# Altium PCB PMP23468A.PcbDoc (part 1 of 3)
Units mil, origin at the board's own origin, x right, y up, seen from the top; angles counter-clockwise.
Board outline 5250 x 3500 mil, 6 copper layers (Top Layer, Signal Layer 1, Signal Layer 2, Signal Layer 3, Signal Layer 4, Bottom Layer), stack 61.8 mil thick; 157 components, 73 nets, 403 pads, 842 vias.
Unrouted connection lines stored in the file: 3.
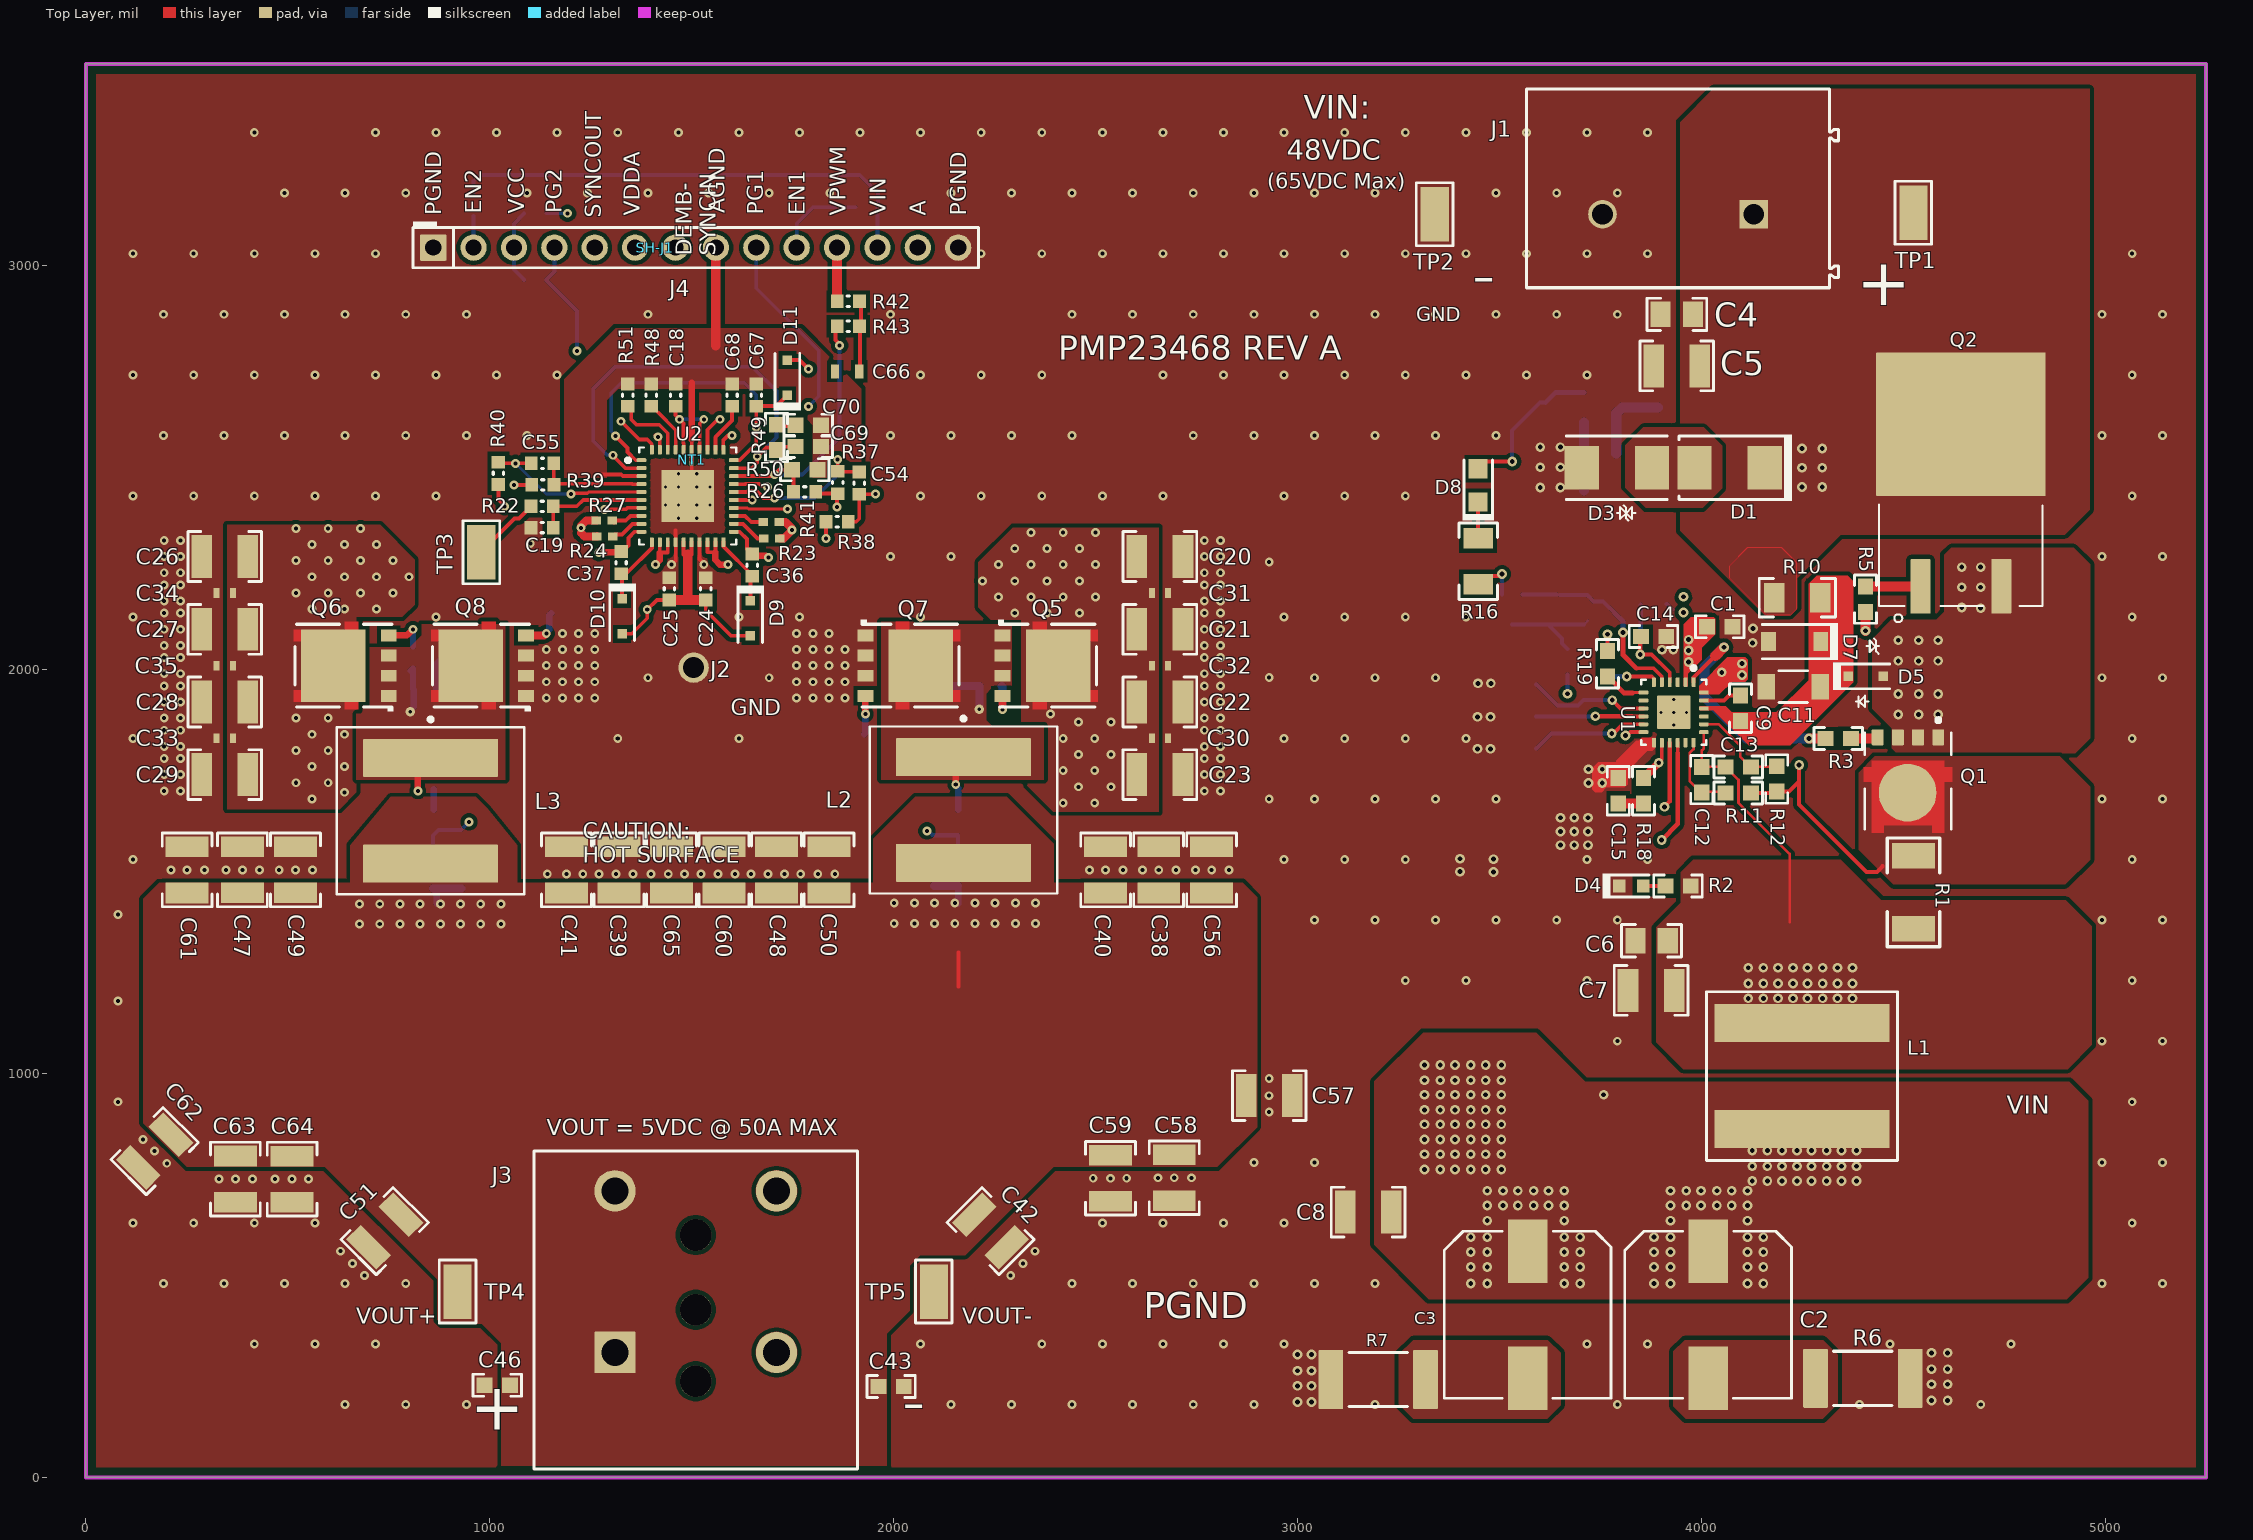
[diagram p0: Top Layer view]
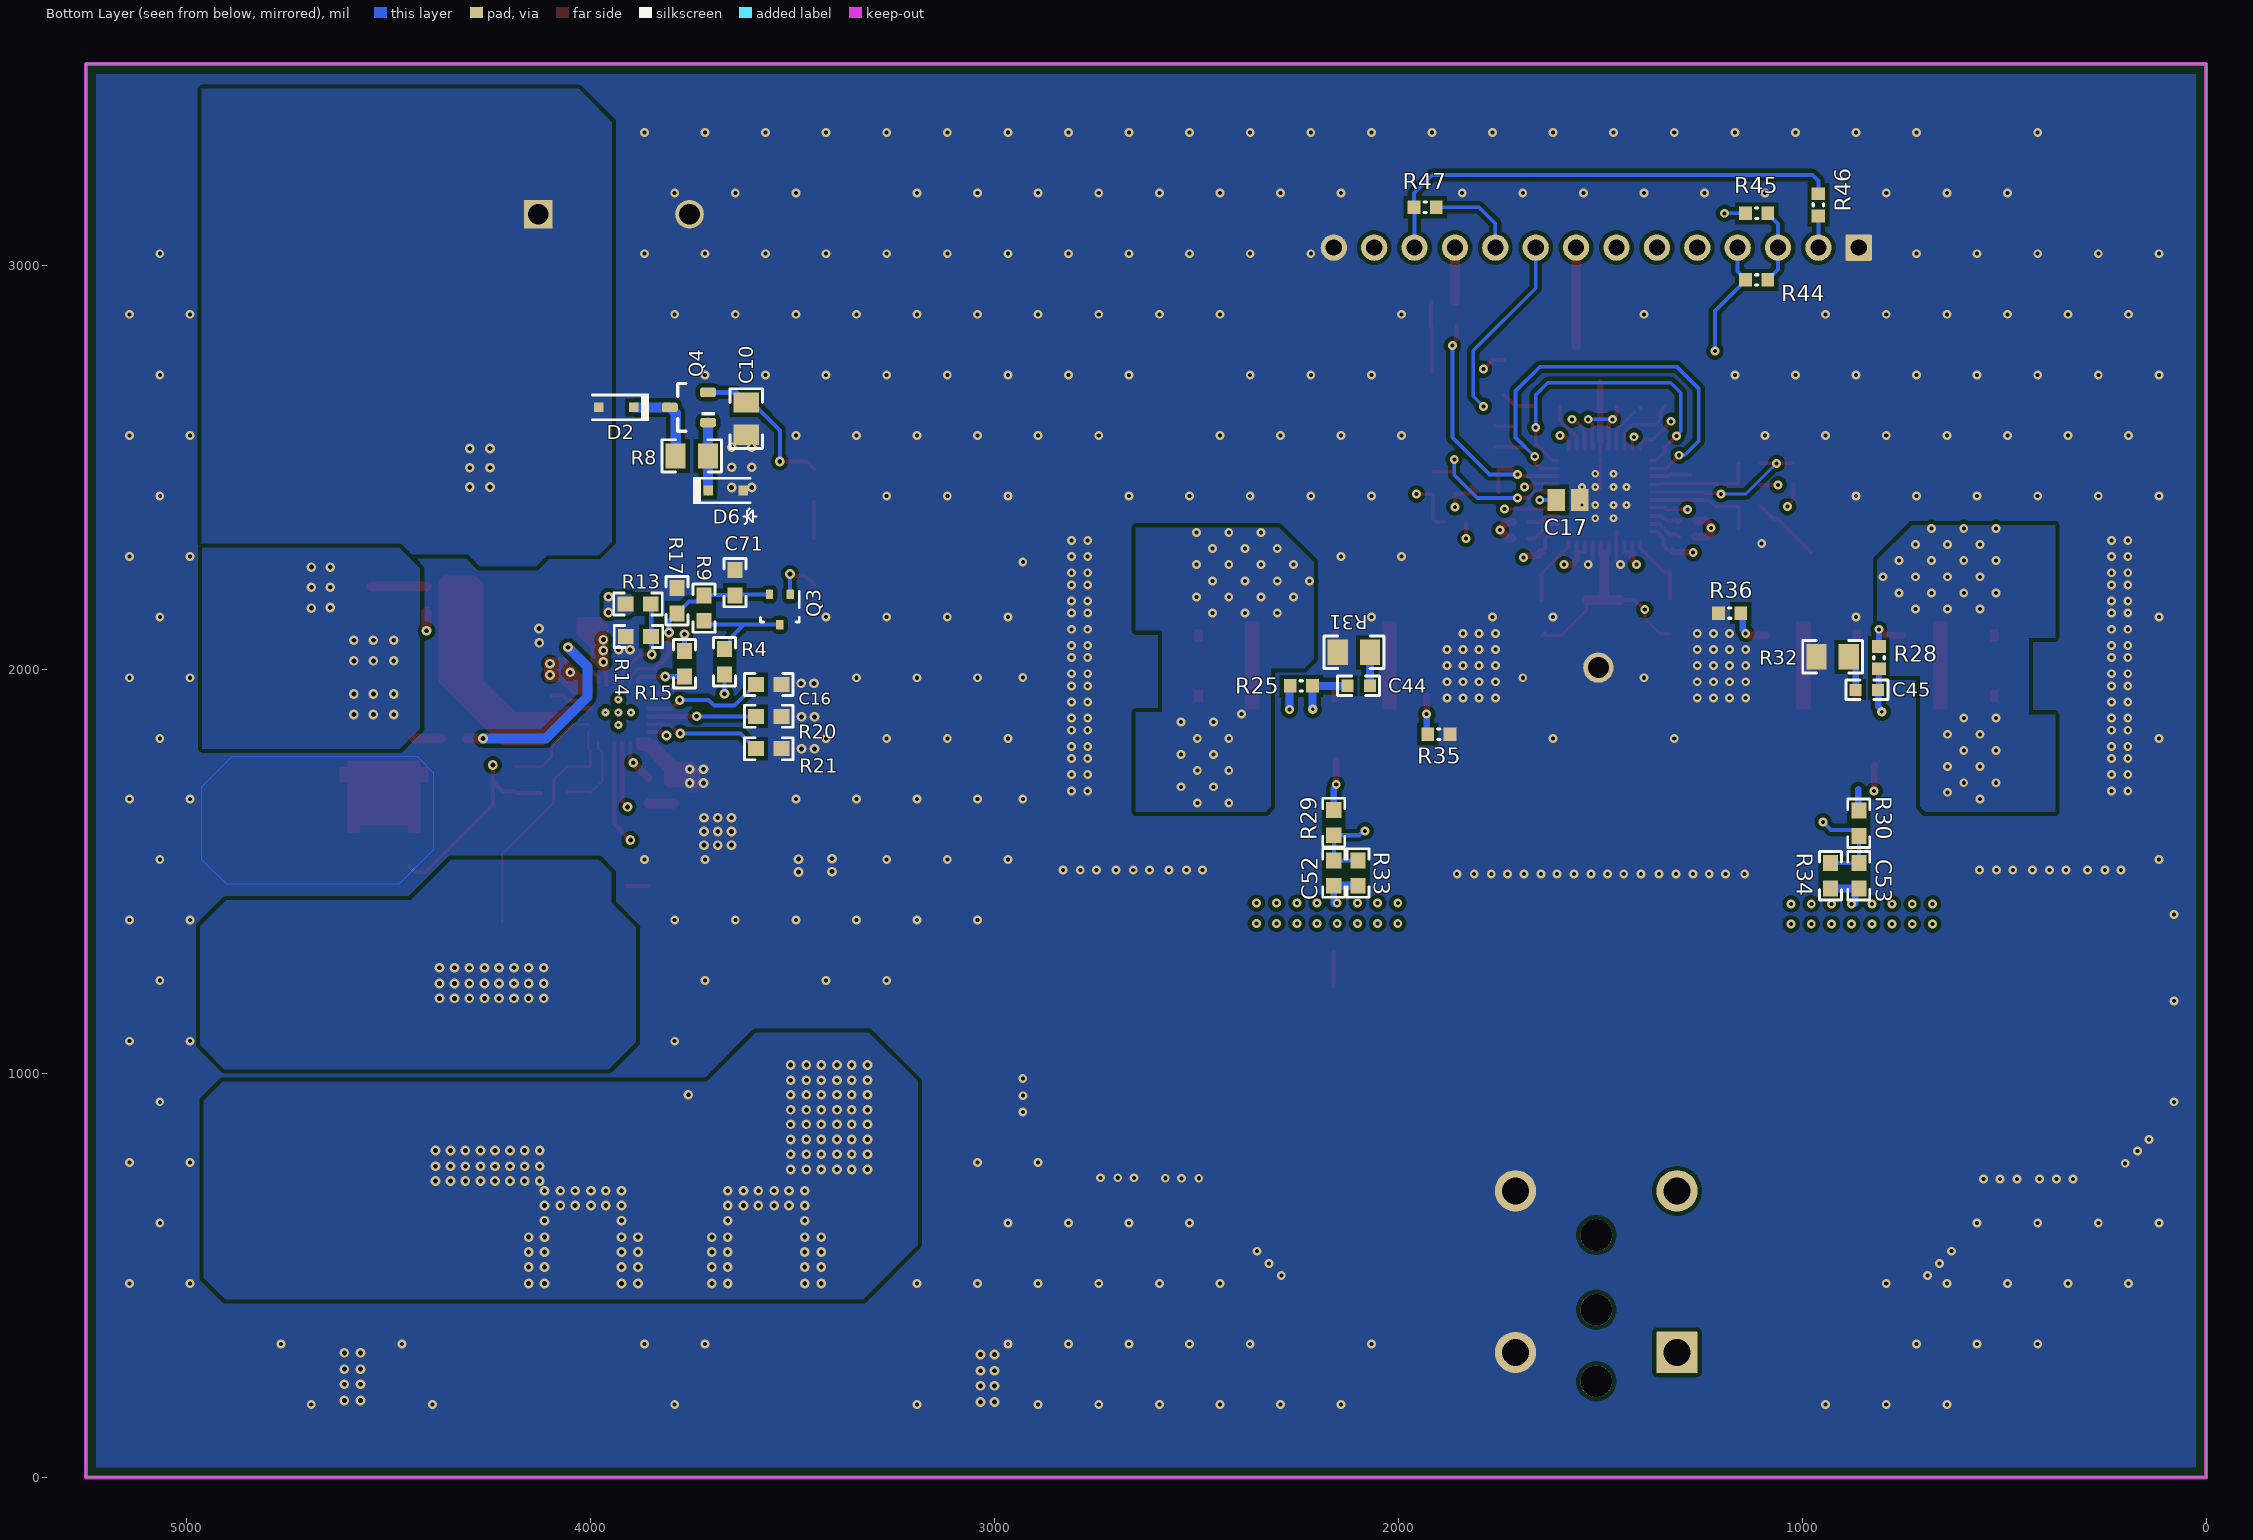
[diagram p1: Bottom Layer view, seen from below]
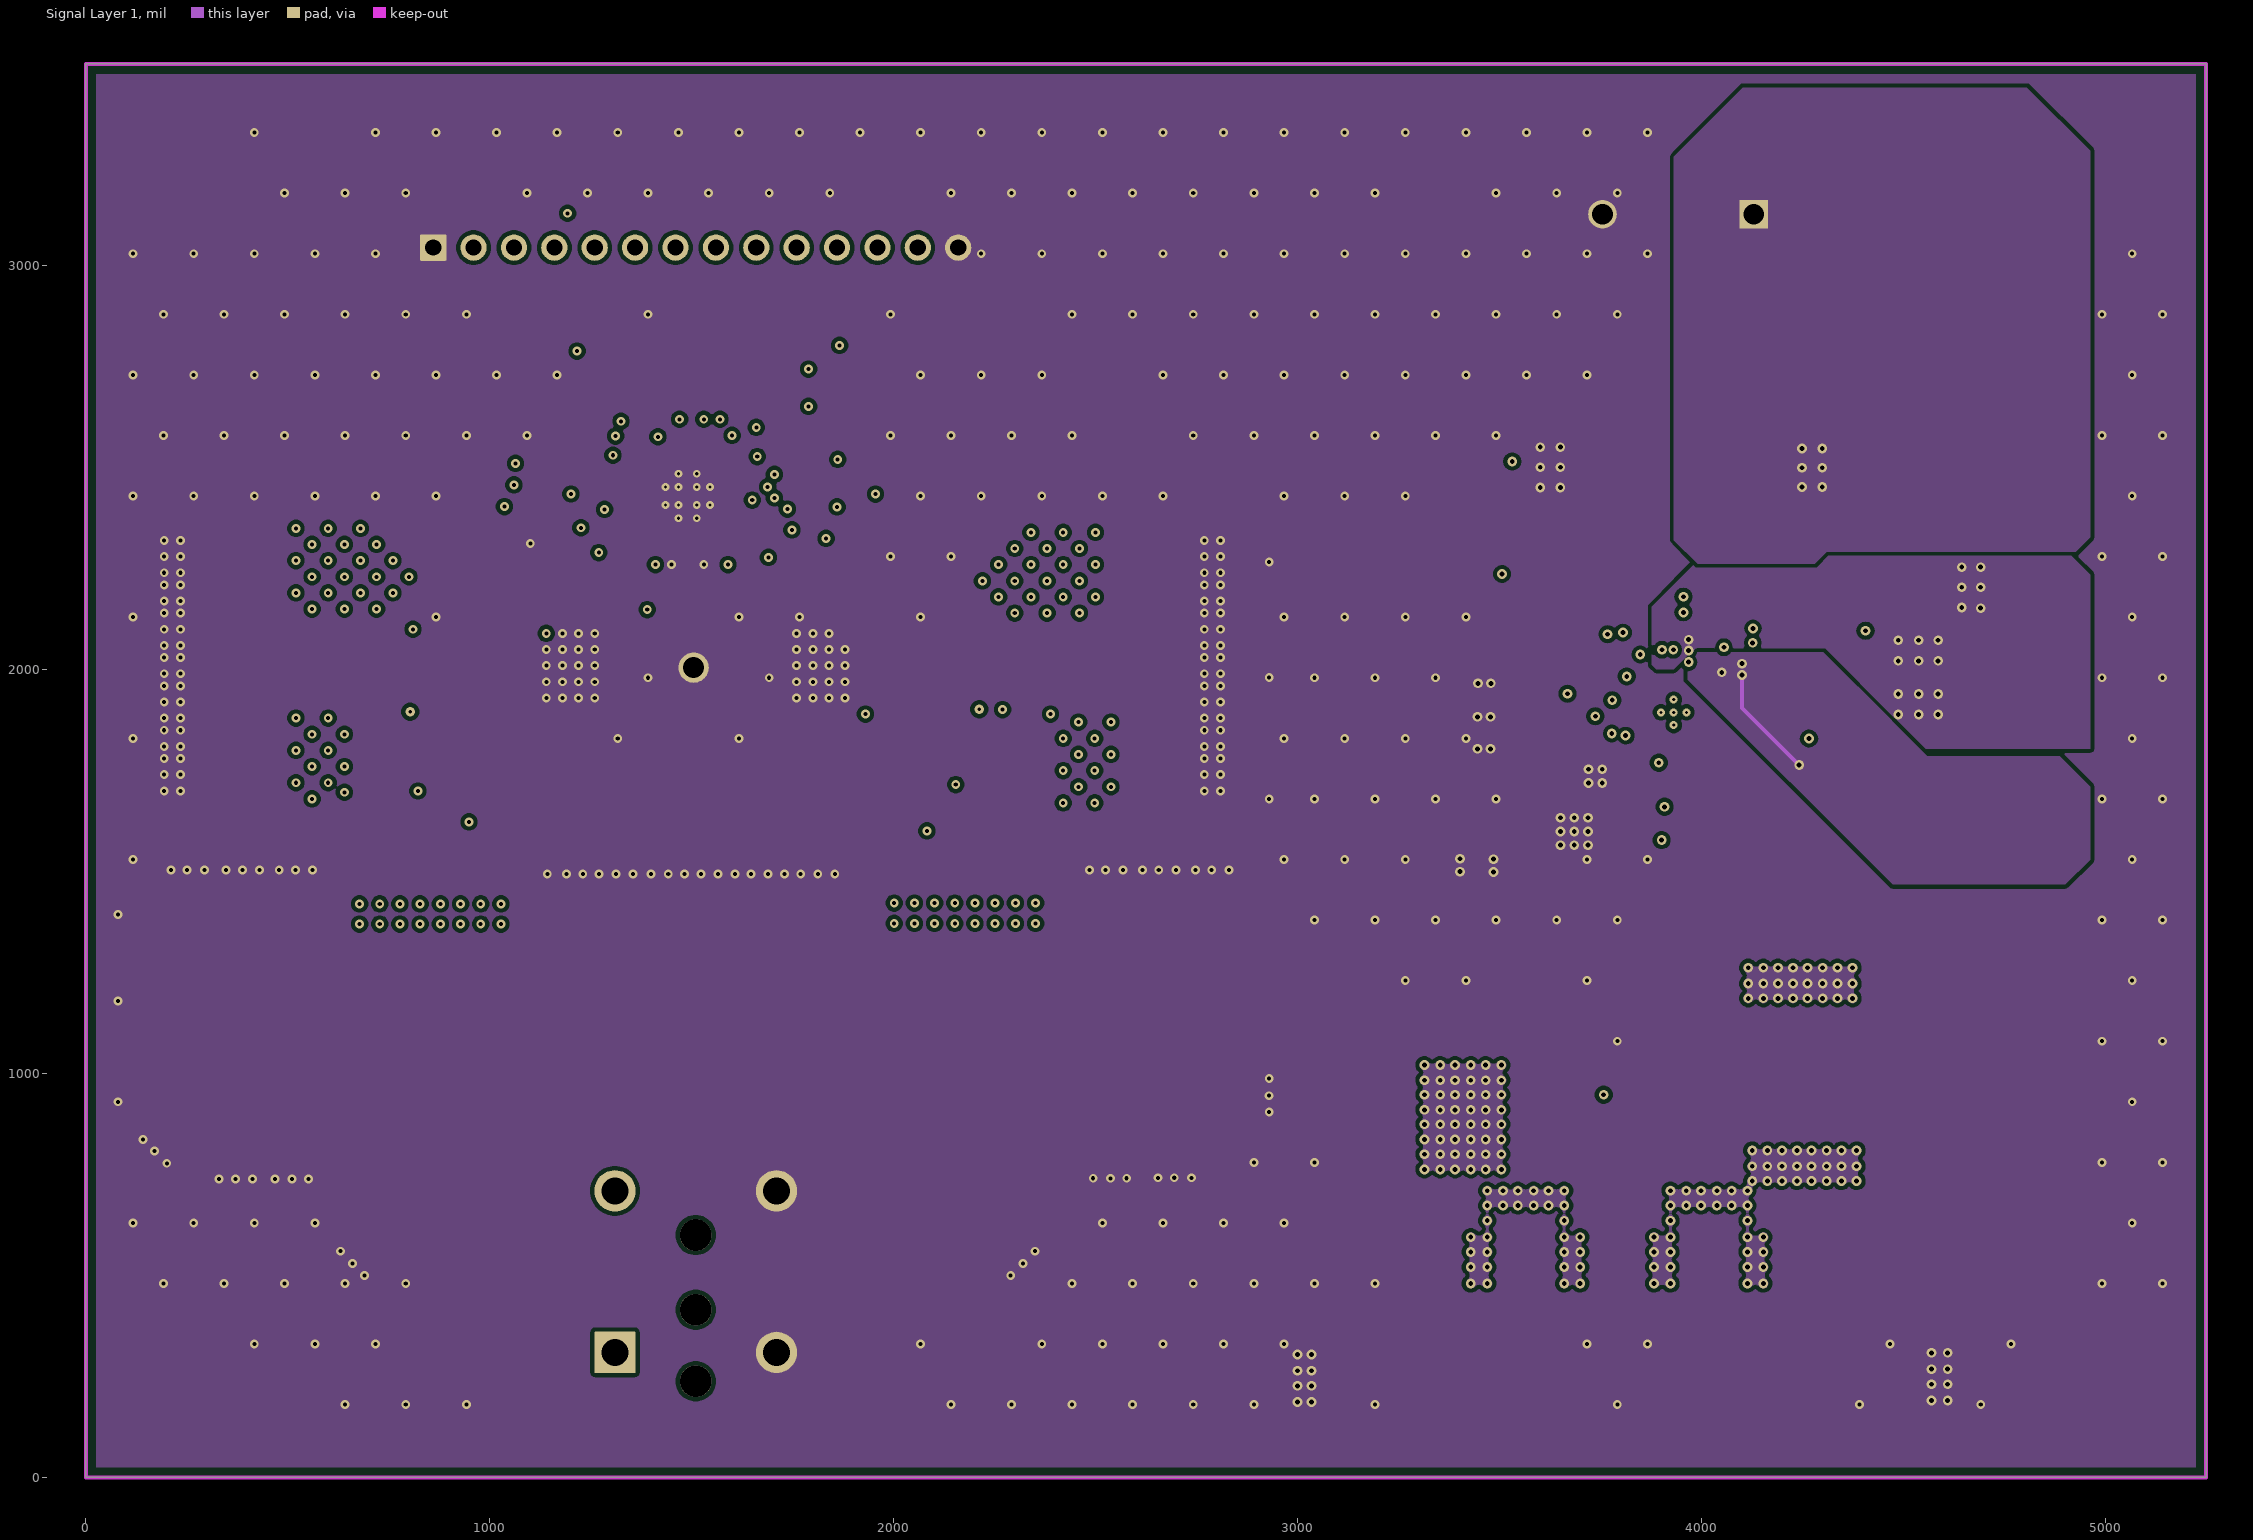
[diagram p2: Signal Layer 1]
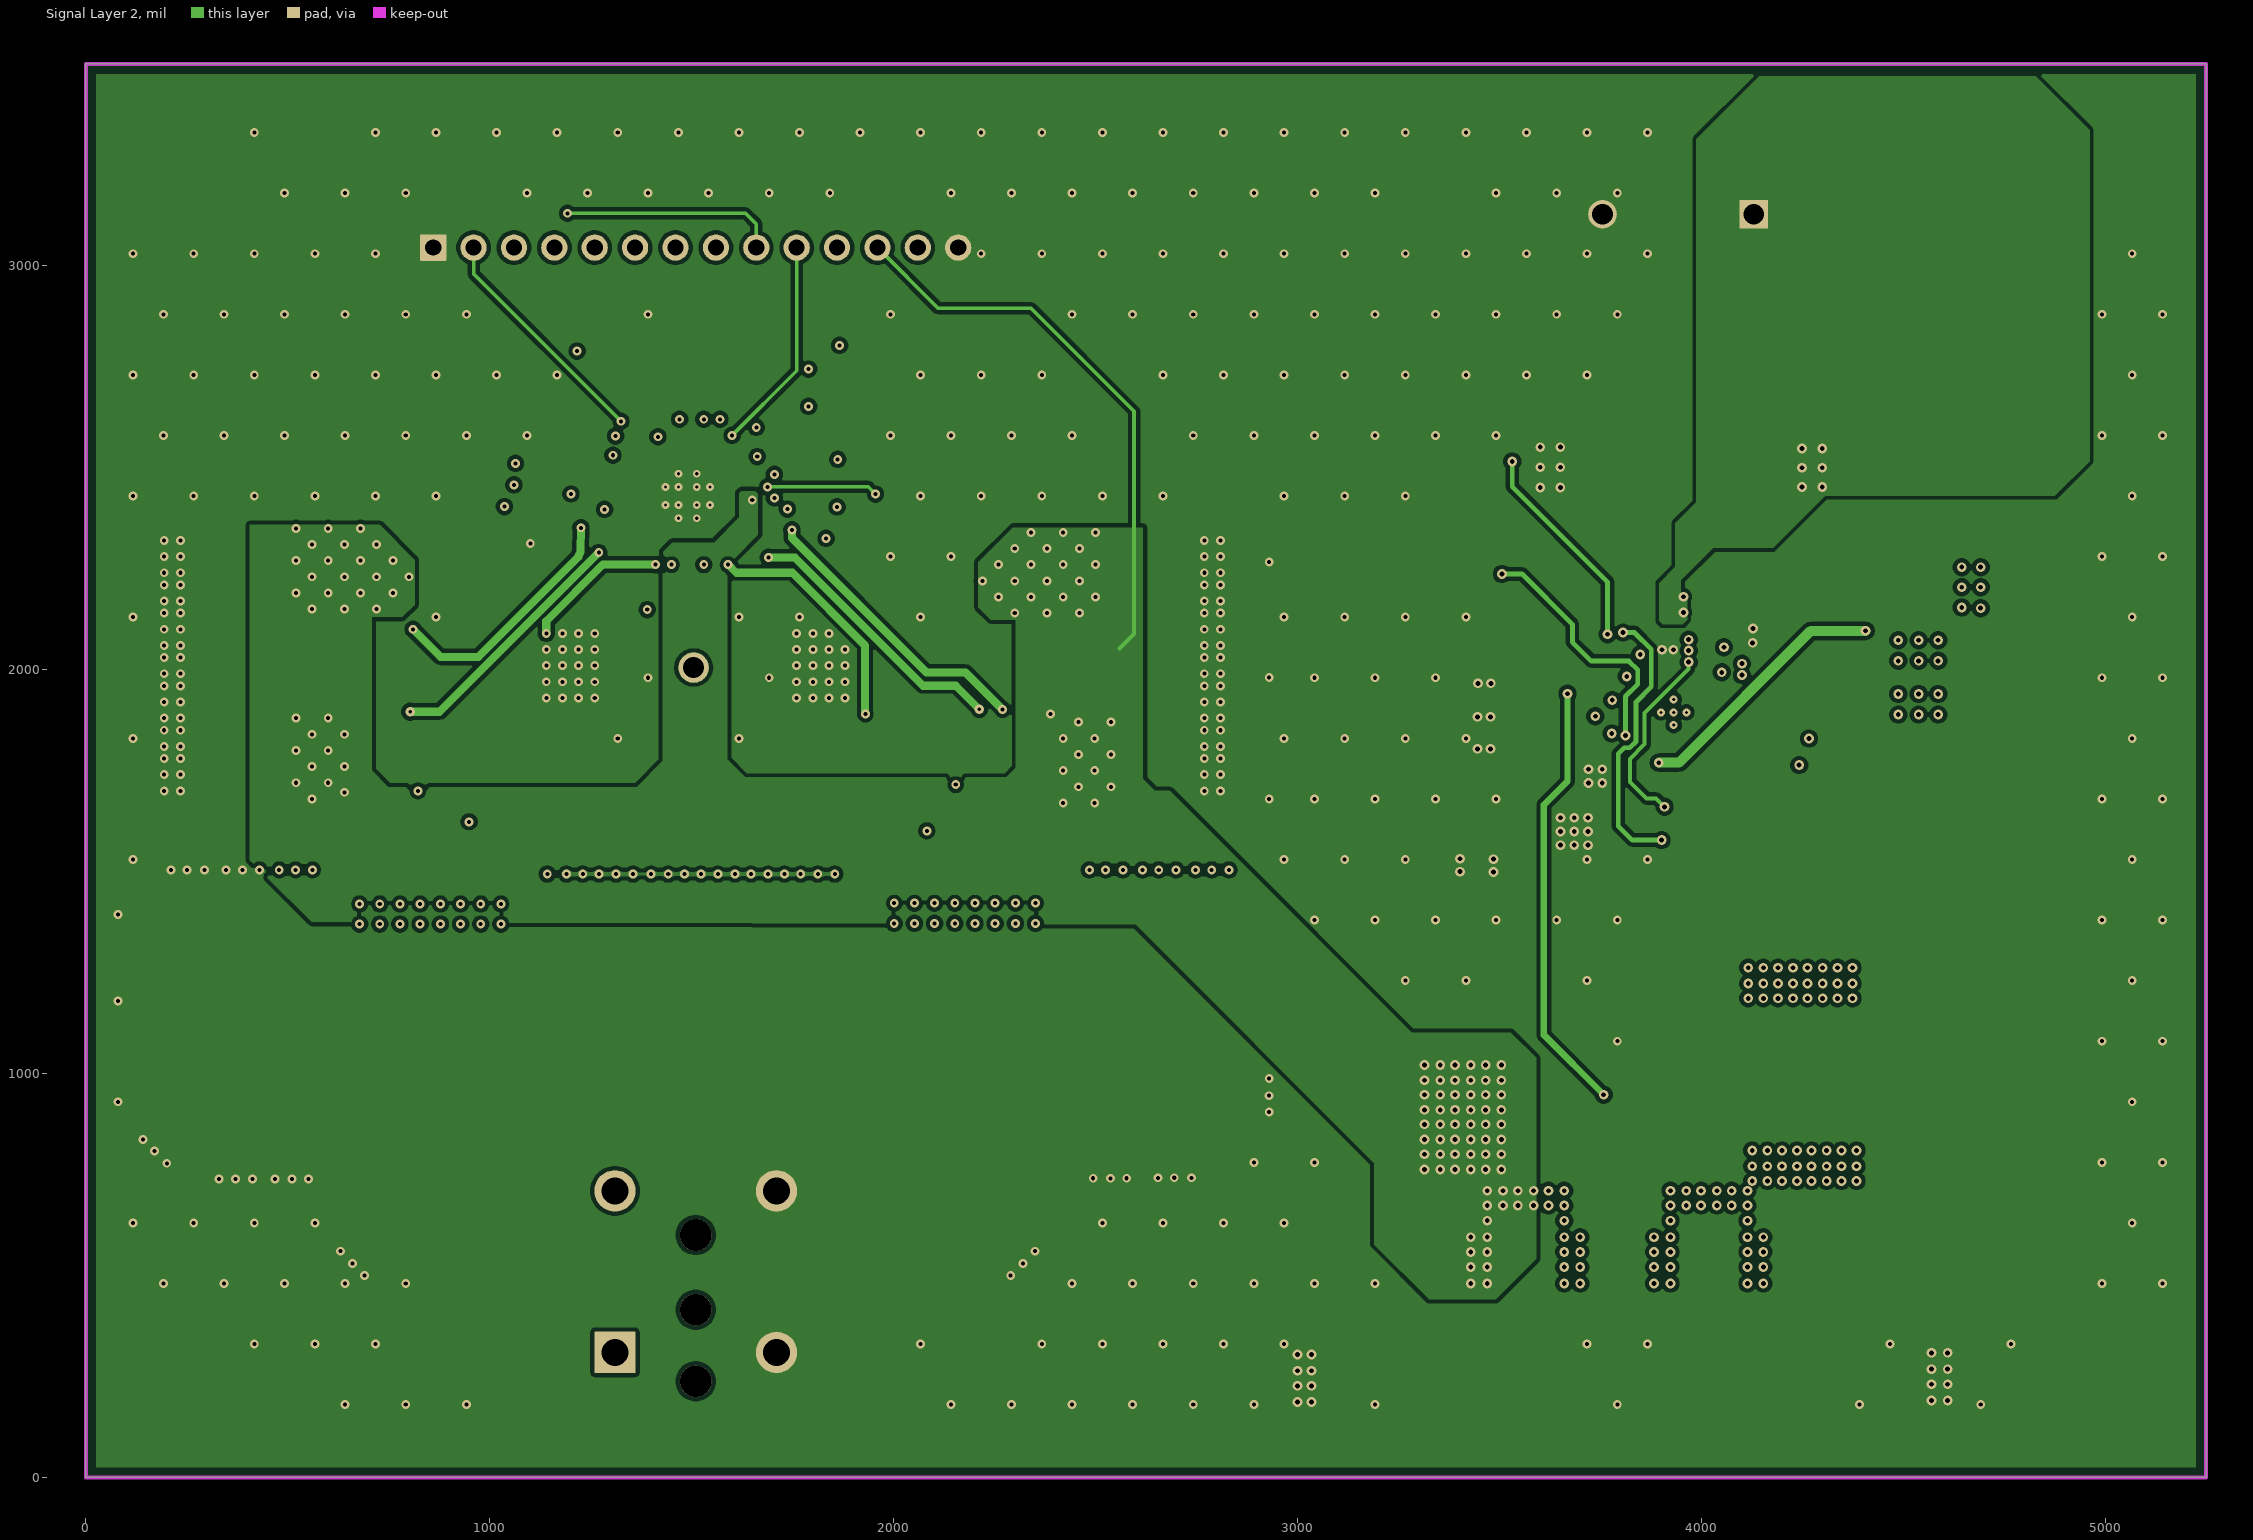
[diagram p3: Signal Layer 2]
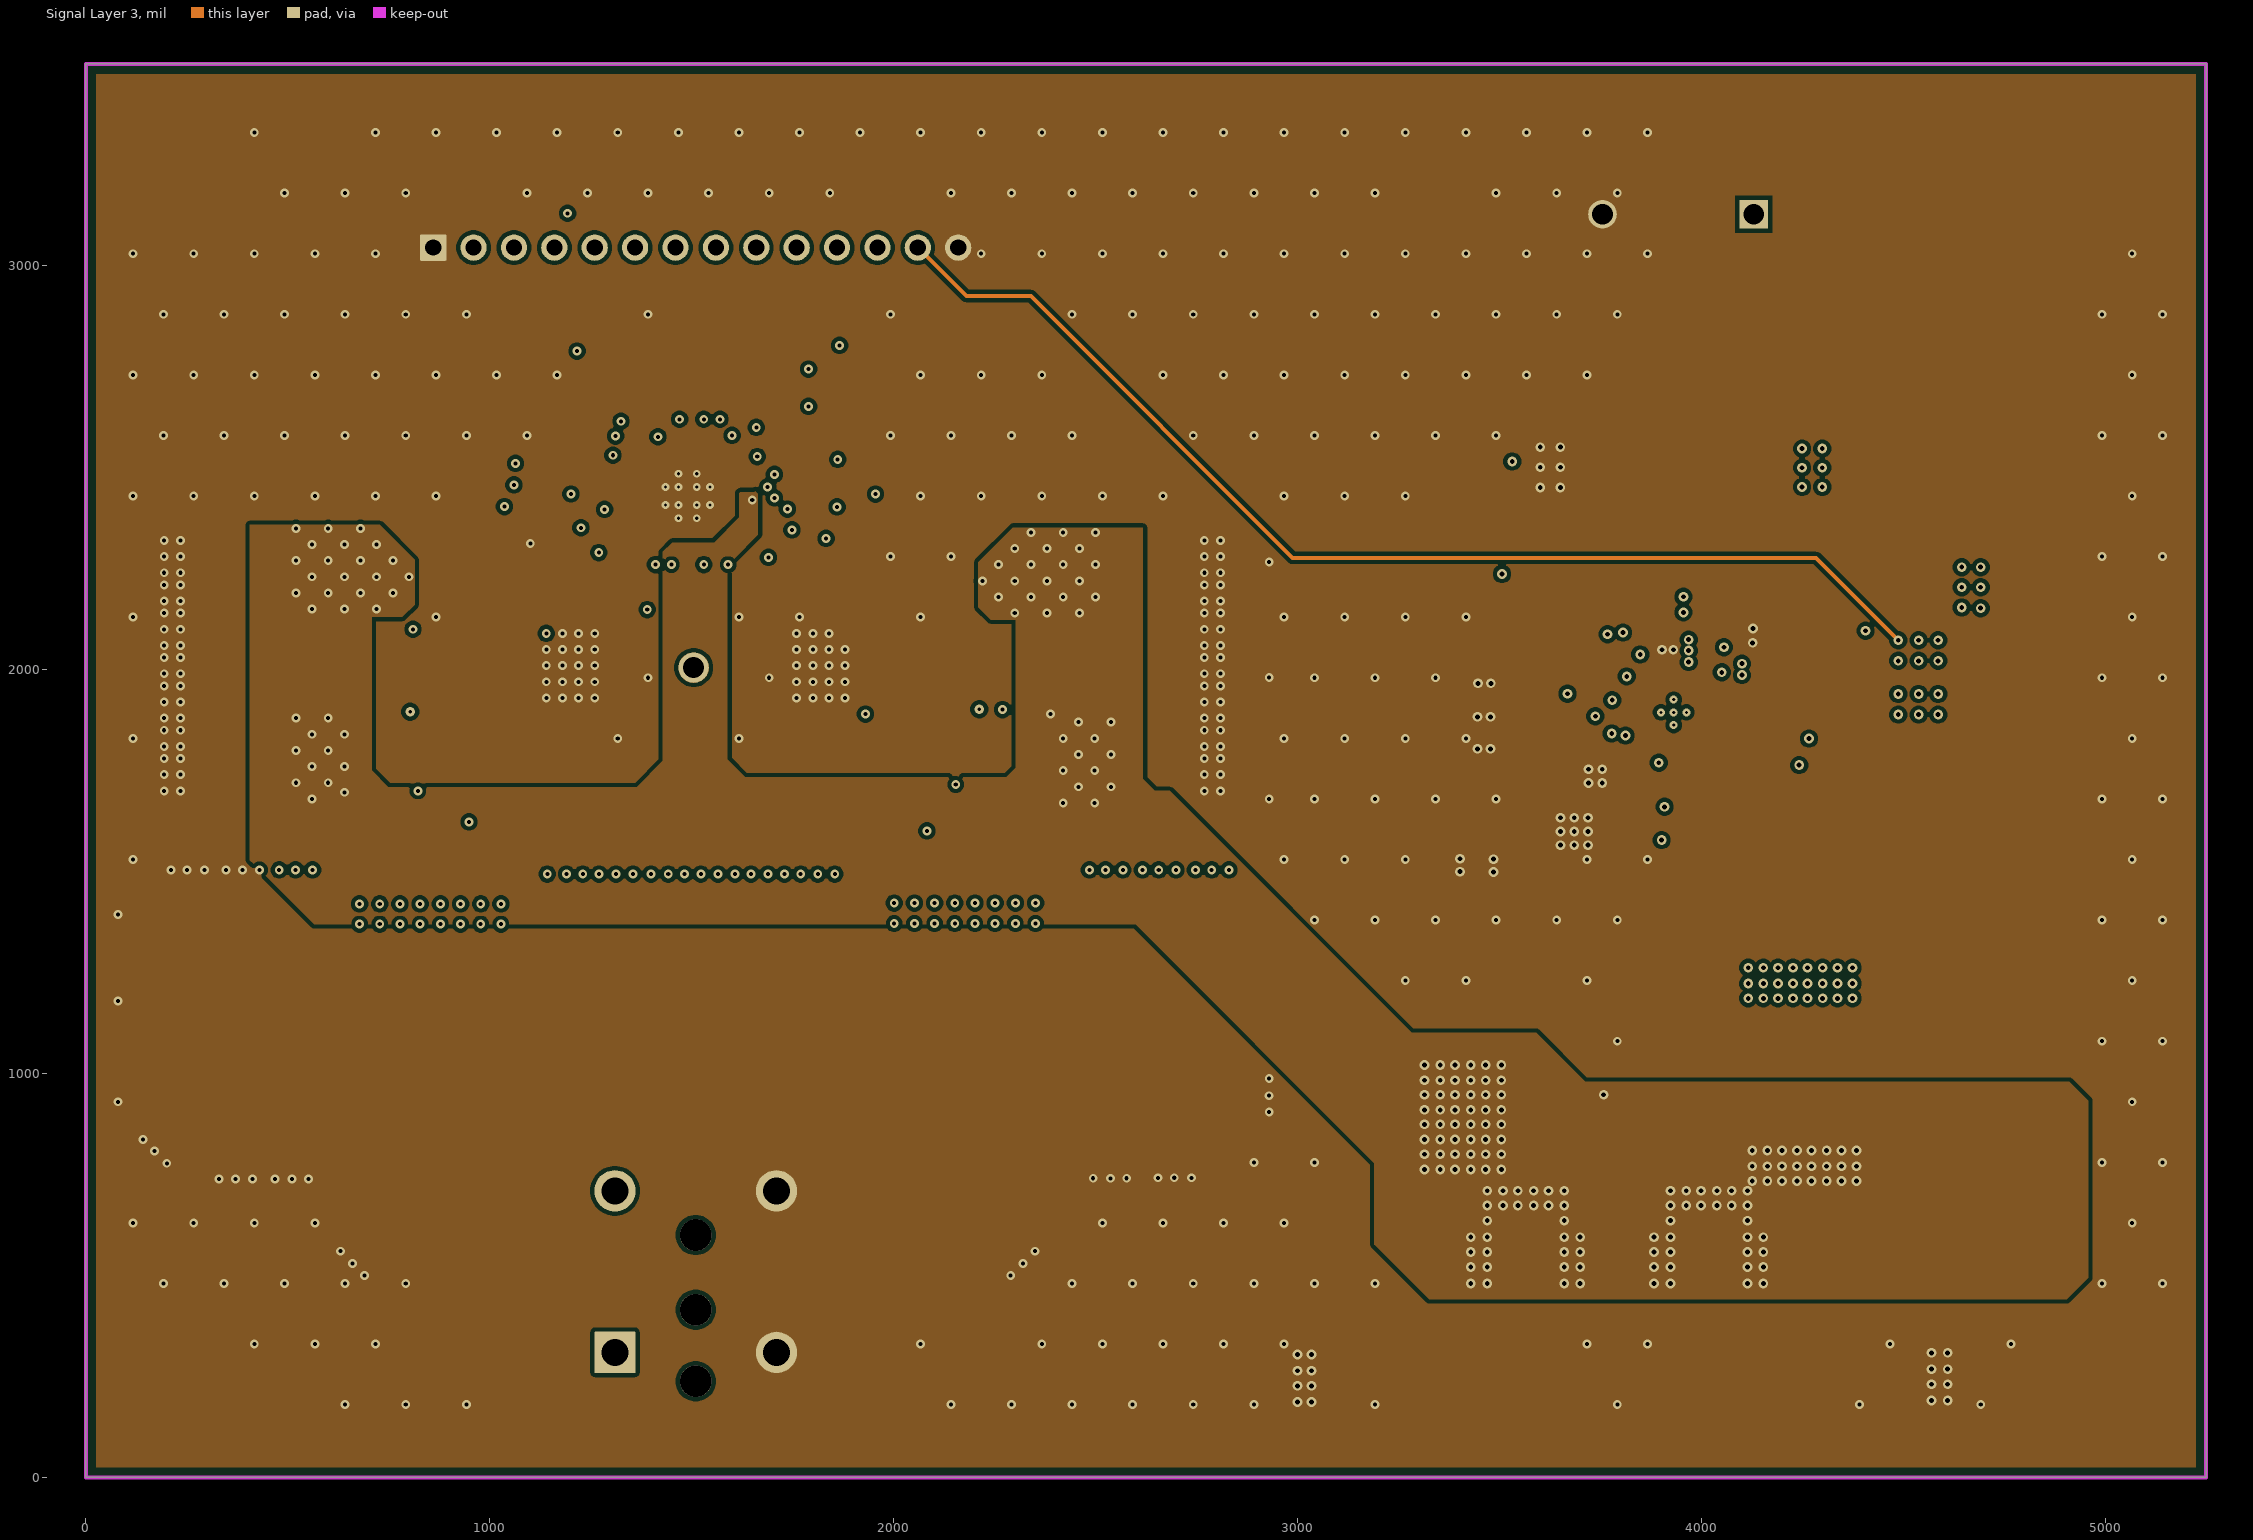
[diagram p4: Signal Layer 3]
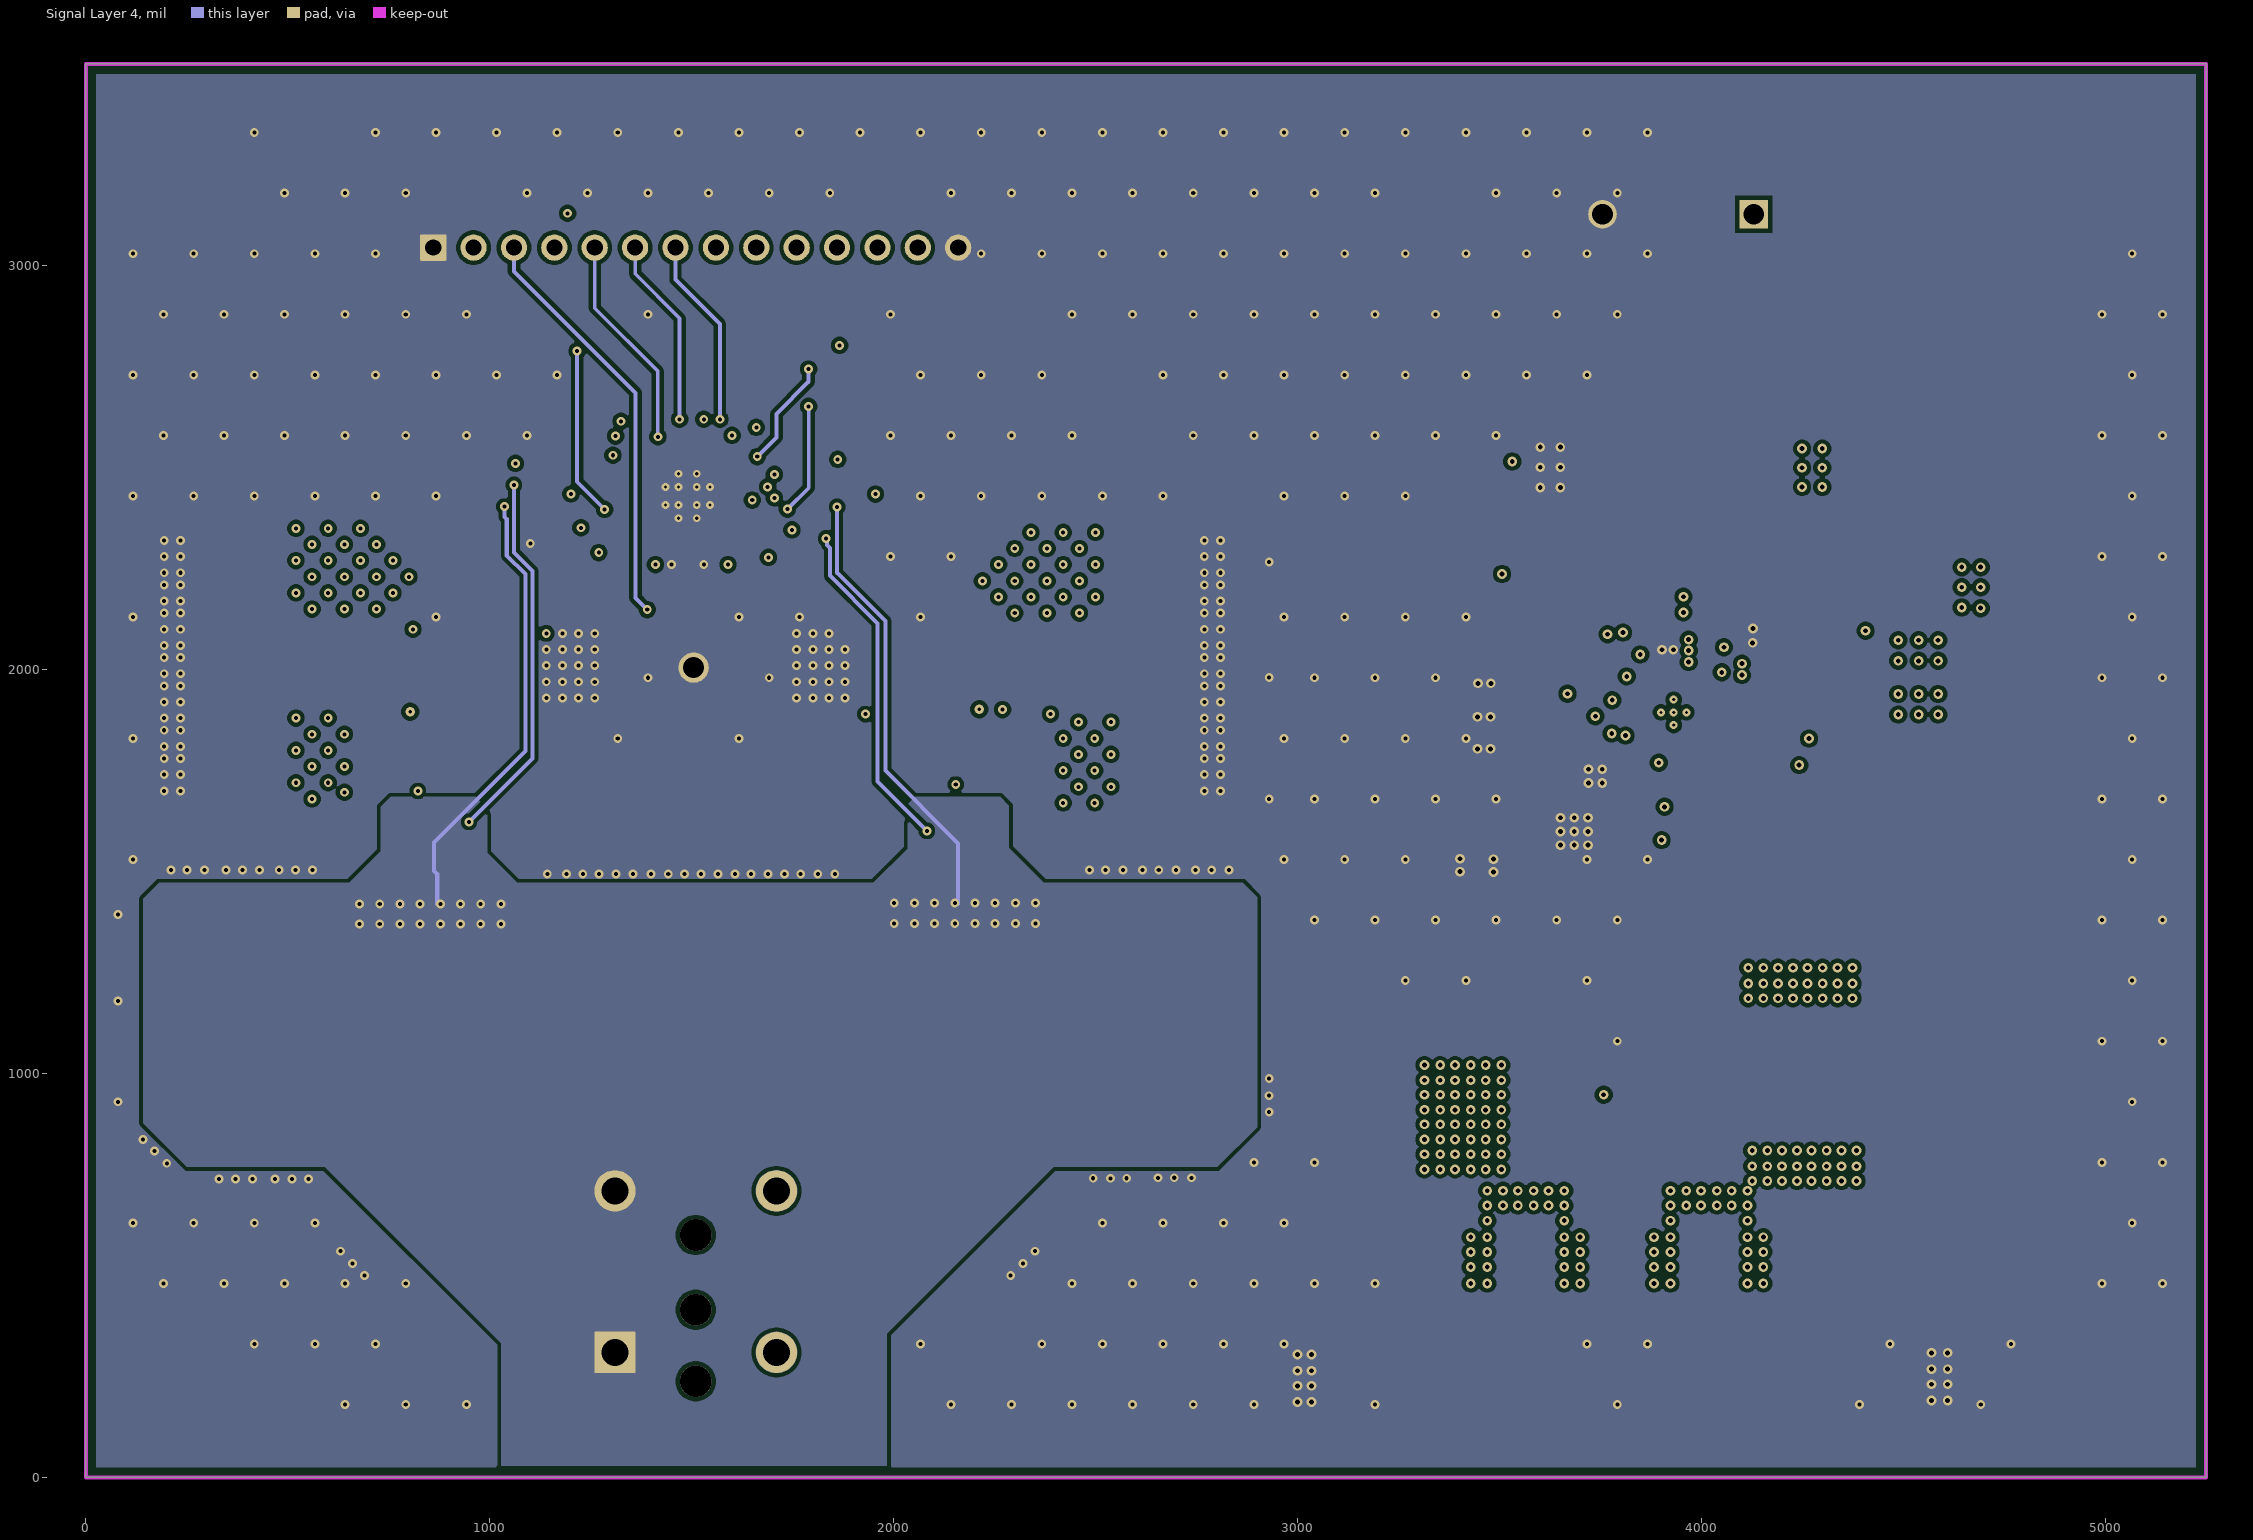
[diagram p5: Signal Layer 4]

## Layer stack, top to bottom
Top Solder: solder mask 0.4, Solder Resist, Dk 3.5
Top Layer: signal copper 2.8
Dielectric1: core 5, FR-4 High Tg, Dk 4.2
Signal Layer 1: signal copper 2.8
Dielectric 2: core 15, FR-4 High Tg, Dk 4.2
Signal Layer 2: signal copper 2.8
Dielectric 3: prepreg 5, FR-4 High Tg, Dk 4.2
Signal Layer 3: signal copper 2.8
Dielectric 4: core 15, FR-4 High Tg, Dk 4.2
Signal Layer 4: signal copper 2.8
Dielectric 5: prepreg 5, FR-4 High Tg, Dk 4.2
Bottom Layer: signal copper 2.8
Bottom Solder: solder mask 0.4, Solder Resist, Dk 3.5

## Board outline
0,0 0,3500 5250,3500 5250,0

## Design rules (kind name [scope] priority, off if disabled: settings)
AcuteAngle [All] p1: minimum=4.50000000000000E+0001 checktracksonly=FALSE
AssemblyTestPointUsage [All] p1: valid=2
BoardOutlineClearance BoardOutlineClearance_MountingHoles [OnCopper and InComponentClass('Mounting Holes')] p1: gap=40 ignorepadtopadclearanceinfootprint=FALSE
BoardOutlineClearance BoardOutlineClearance_Poly [OnCopper and IsPoly] p2: gap=25 ignorepadtopadclearanceinfootprint=FALSE
BoardOutlineClearance [OnCopper and Not InComponentClass('Logo') and not InComponentClass('FiducialMark') and not InRegion(1000,500,4000,800) and not InPoly] p3: gap=50 ignorepadtopadclearanceinfootprint=FALSE
Clearance "Clearance_EMI 2 Poly" [InNetClass('EMI-Clearance')] p1: gap=19.68 ignorepadtopadclearanceinfootprint=FALSE
Clearance Clearance_Keepouts [((IsTrack Or IsArc) And Not InPoly) And IsFree and IsKeepOut vs ((IsTrack Or IsArc) And Not InPoly) And IsFree and IsKeepOut] p2: gap=40 ignorepadtopadclearanceinfootprint=FALSE
Clearance Clearance_Poly [InPolygon] p3: gap=10 ignorepadtopadclearanceinfootprint=FALSE
Clearance Clearance_FiducialMark [IsKeepOut and InComponentClass('FiducialMark') vs IsPad and InComponentClass('FiducialMark')] p4: gap=0 ignorepadtopadclearanceinfootprint=FALSE
Clearance Clearance_MtgHole [HasFootprint('NY PMS 440 0025 PH') vs HasFootprint ('Keystone_1902C')] p5: gap=0 ignorepadtopadclearanceinfootprint=FALSE
Clearance [All] p6: gap=7.87 ignorepadtopadclearanceinfootprint=FALSE except(0: Arc-Hole Track-Hole SMDPad-Hole THPad-Hole Via-Hole Fill-Hole Poly-Hole Region-Hole Text-Hole)
ComponentClearance ComponentClearance_FETPad [HasFootprint('SO-8FL') vs HasFootprint('SO-8FL')] p1: gap=0 collisioncheckmode=3 verticalgap=0 showdistances=FALSE
ComponentClearance "ComponentClearance_Sheild H2" [InComponentClass('VOUT2') vs InComponent('H2')] p2: gap=20 collisioncheckmode=3 verticalgap=5 showdistances=FALSE
ComponentClearance "ComponentClearance_Shield H1" [InComponentClass('VOUT1') vs InComponent('H1')] p3: gap=20 collisioncheckmode=3 verticalgap=5 showdistances=FALSE
ComponentClearance ComponentClearance_NetTie [HasFootprint('RHA0040N-MFG') vs HasFootprint('Net-Tie_10mil')] p4: gap=0 collisioncheckmode=3 verticalgap=0 showdistances=FALSE
ComponentClearance ComponentClearance_MountingHoles_FiducialMarks [InComponentClass('Mounting Holes') vs InComponentClass('FiducialMark')] p5: gap=50 collisioncheckmode=3 verticalgap=10 showdistances=FALSE
ComponentClearance ComponentClearance_Shunt [InComponentClass('Header') vs InComponentClass('Shunt')] p6: gap=0 collisioncheckmode=3 verticalgap=0 showdistances=FALSE
ComponentClearance ComponentClearance_Logo [InComponentClass('Logo')] p7: gap=50 collisioncheckmode=3 verticalgap=10 showdistances=FALSE
ComponentClearance ComponentClearance_ScrewToNut [(HasFootprint('NY PMS 440 0025 PH')) vs (HasFootprint('Keystone_1902C'))] p8: gap=5 collisioncheckmode=3 verticalgap=10 showdistances=FALSE
ComponentClearance ComponentClearance_MountingHoles [InComponentClass('Mounting Holes')] p9: gap=100 collisioncheckmode=3 verticalgap=100000 showdistances=FALSE
ComponentClearance ComponentClearance_SmallPassives [HasFootprint('0201*') or HasFootprint('0402*') or HasFootprint('0508') or HasFootprint('0603*') or HasFootprint('0612') or HasFootprint('0805*') or HasFootprint('0815*') or HasFootprint('0830*') or HasFootprint('1206*') or HasFootprint('1210*') or HasFootprint('1808*') or HasFootprint('1812*') or HasFootprint('1825*') or HasFootprint('2010*') or HasFootprint('2220*') or HasFootprint('2225*') or HasFootprint('2512*') or HasFootprint('2728*') or HasFootprint('3518*') vs HasFootprint('0201*') or HasFootprint('0402*') or HasFootprint('0508') or HasFootprint('0603*') or HasFootprint('0612') or HasFootprint('0805*') or HasFootprint('0815*') or HasFootprint('0830*') or HasFootprint('1206*') or HasFootprint('1210*') or HasFootprint('1808*') or HasFootprint('1812*') or HasFootprint('1825*') or HasFootprint('2010*') or HasFootprint('2220*') or HasFootprint('2225*') or HasFootprint('2512*') or HasFootprint('2728*') or HasFootprint('3518*')] p10: gap=14.96 collisioncheckmode=3 verticalgap=10 showdistances=FALSE
ComponentClearance ComponentClearance_Shuint [HasFootprint('TSW-114-07-G-S') vs HasFootprint('Harwin_M7582-05')] p11: gap=0 collisioncheckmode=3 verticalgap=0 showdistances=FALSE
ComponentClearance ComponentClearance_THtoTH [IsThruComponent vs IsThruComponent] p12: gap=30 collisioncheckmode=3 verticalgap=30 showdistances=FALSE
ComponentClearance [All] p13: gap=30 collisioncheckmode=3 verticalgap=10 showdistances=FALSE
DiffPairsRouting [All] p1: maxlimit=100 minlimit=10 mostfreqgap=10 toplayer_minwidth=15 toplayer_maxwidth=15 toplayer_prefwidth=15 midlayer1_minwidth=15 midlayer1_maxwidth=15 midlayer1_prefwidth=15 midlayer2_minwidth=15 midlayer2_maxwidth=15 midlayer2_prefwidth=15 midlayer3_minwidth=15 midlayer3_maxwidth=15 midlayer3_prefwidth=15 midlayer4_minwidth=15 midlayer4_maxwidth=15 midlayer4_prefwidth=15 bottomlayer_minwidth=15 bottomlayer_maxwidth=15 bottomlayer_prefwidth=15 maxuncoupledlength=1000
FabricationTestPointUsage TestPointUsage [All] p1: valid=2 allowmultiple=FALSE
FabricationTestpoint Testpoint [All] p1: side=3 testpointundercomponent=TRUE minsize=40 maxsize=100 preferedsize=60 minholesize=0 maxholesize=40 preferedholesize=32 testpointgrid=1 allowsidetop=TRUE allowsidebottom=TRUE usegrid=TRUE gridtolerance=0.01
FanoutControl Fanout_LCC [IsLCC] p1: bgadir=Out bgaviamode=Centered fanoutstyle=Auto fanoutdirection=Alternating viagrid=1 // Fanout_LCC (Default Rule)
FanoutControl Fanout_BGA [IsBGA] p2: bgadir=Out bgaviamode=Centered fanoutstyle=Auto fanoutdirection=Alternating viagrid=1 // Fanout_BGA (Default Rule)
FanoutControl Fanout_Default [All] p4: bgadir=Out bgaviamode=Centered fanoutstyle=Auto fanoutdirection=Alternating viagrid=1 // Fanout_Default (Default Rule)
FanoutControl Fanout_Small [(CompPinCount < 5)] p5: bgadir=Out bgaviamode=Centered fanoutstyle=Auto fanoutdirection=OutThenIn viagrid=1 // Fanout_Small (Default Rule)
Height [All] p1: minheight=0 maxheight=2000 prefheight=500
HoleSize [All] p1: absolutevalues=TRUE maxlimit=251 minlimit=7.87 maxpercent=80.000 minpercent=20.000
MinimumAnnularRing MinimumAnnularRing_ThermalPadVias [IsVia and InAnyComponent] p1: minimumring=5.91
MinimumAnnularRing [All] p2: minimumring=6
MinimumSolderMaskSliver MinimumSolderMaskSliver_Logo [InComponentClass('Logo') vs InComponentClass('Logo')] p1: minsoldermaskwidth=0.7
MinimumSolderMaskSliver [All] p2: minsoldermaskwidth=3.94
PlaneClearance [All] p1: clearance=10
PlaneConnect [All] p1: planeconnectstyle=Relief reliefexpansion=10 reliefentries=4 reliefconductorwidth=10 reliefairgap=10
PolygonConnect [All] p1: connectstyle=Direct reliefconductorwidth=10 reliefentries=4 polygonreliefangle="90 Angle" airgapwidth=10
RoutingVias [All] p1: holewidth=10 width=22 viastyle="Through Hole" minholewidth=7.87 minwidth=20 maxholewidth=40 maxwidth=65
SilkToBoardRegionClearance [Not ((IsComment or IsDesignator) And (Hide <> 'False')) and not InRegion(1000,500,4000,800)] p1:
SilkToSilkClearance SilkToSilkClearance_Pb-FreeLogo [(HasFootprint('Pb-Free_Overlay_Medium') OR HasFootprint('Pb-Free_Overlay_Small')) vs (HasFootprint('Pb-Free_Overlay_Medium') OR HasFootprint('Pb-Free_Overlay_Small'))] p1: silktosilkclearance=0
SilkToSilkClearance [All] p2: silktosilkclearance=4
SilkToSolderMaskClearance [IsPad] p1: minsilkscreentomaskgap=3.9 clearancetoexposedcopper=TRUE
SilkToSolderMaskClearance SilkToComponentPadClearance [(IsPad or IsFill or IsRegion) and InAnycomponent] p2: minsilkscreentomaskgap=3.9 clearancetoexposedcopper=TRUE
SolderMaskExpansion [All] p1: expansion=1.97 istentingtop=FALSE
Width [All] p1: maxlimit=100 minlimit=6 preferedwidth=10 checkconnectedcopper=TRUE
13 further rules are at their usual default settings.

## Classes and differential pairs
component class PMP23468-SH1: C1 C2 C3 C4 C5 C6 C7 C8 C9 C10 C11 C12 C13 C14 C15 C16 C71 C202 C204 C205 C206 C207 C208 D1 D2 D3 D4 D5 D6 D7 D8 J1 J201 L1 L201 Q1 Q2 Q3 Q4 R1 R2 R3 R4 R5 R6 R7 R8 R9 R10 R11 R12 R13 R14 R15 R16 R17 R18 R19 R20 R21 R206 TP1 TP2 U1
component class Header: J4
component class PMP23468-SH2: C17 C18 C19 C20 C21 C22 C23 C24 C25 C26 C27 C28 C29 C30 C31 C32 C33 C34 C35 C36 C37 C38 C39 C40 C41 C42 C43 C44 C45 C46 C47 C48 C49 C50 C51 C52 C53 C54 C55 C56 C57 C58 C59 C60 C61 C62 C63 C64 C65 C66 C67 C68 C69 C70 D9 D10 D11 J2 J3 J4 J201 L2 L3 NT1 Q5 Q6 Q7 Q8 R22 R23 R24 R25 R26 R27 R28 R29 R30 R31 R32 R33 R34 R35 R36 R37 R38 R39 R40 R41 R42 R43 R44 R45 R46 R47 R48 R49 R50 R51 R206 SH-J1 TP3 TP4 TP5 U2

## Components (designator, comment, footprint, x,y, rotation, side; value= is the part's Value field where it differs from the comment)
C1 "GCJ188L8EL104KA07D" 0603 4045.71,2106.32 r0 top value=0.1uF
C2 "EEHZC1J560P" SM_RADIAL_10BMM 4017.03,402.69 r270 top value=56uF
C3 "EEHZC1J560P" SM_RADIAL_10BMM 3570,402.69 r270 top value=56uF
C4 "C0805C104K1RACTU" 0805_HV 3939.3,2879.7 r0 top value=0.1uF
C5 "GCM32DC72A475KE02L" 1210_220 3939.3,2752.27 r180 top value=4.7uF
C6 "C0805C104K1RACTU" 0805_HV 3876.78,1328.77 r180 top value=0.1uF
C7 "GCM32DC72A475KE02L" 1210_220 3875.68,1205.82 r180 top value=4.7uF
C8 "GCM32DC72A475KE02L" 1210_220 3175.11,656.65 r180 top value=4.7uF
C9 "CGA3E2X7R1E104K080AA" 0603 4096.71,1904.32 r90 top value=0.1uF
C10 "GCM21BR71E225KA73L" 0805_HV 3614.71,2621.72 r270 bottom value=2.2uF
C11 "GCM31CR72A105KA03" 1206_180 4227.66,1957.89 r180 top value=1uF
C12 "GRM188R71E332KA01D" 0603 4001.21,1727.82 r90 top value=3300pF
C13 "GCM188R71H103KA37D" 0603 4091.71,1759.32 r180 top value=0.01uF
C14 "C0603C223K3RACTU" 0603 3881.71,2082.32 r0 top value=0.022uF
C15 "CGA3E2X7R2A103K080AA" 0603 3794.32,1700.32 r90 top value=0.01uF
C16 "CGA3E3X7S2A473K080AB" 0603 3559.25,1963.22 r180 bottom value=0.047uF
C17 "GRM21BR72A474KA73L" 0805L 1580,2420 r0 bottom value=0.47uF
C18 "GCM188R71C474KA55D" 0603L 1460,2680 r270 top value=0.47uF
C19 "GRM188R71A225KE15D" 0603L 1130,2351.98 r180 top value=2.2uF
C20 "GCM32DC72A475KE02L" 1210_220 2659.34,2280 r0 top value=4.7uF
C21 "GCM32DC72A475KE02L" 1210_220 2659.34,2100 r0 top value=4.7uF
C22 "GCM32DC72A475KE02L" 1210_220 2659.34,1920 r0 top value=4.7uF
C23 "GCM32DC72A475KE02L" 1210_220 2659.34,1740 r0 top value=4.7uF
C24 "GRM188R71A225KE15D" 0603L 1535,2200 r90 top value=2.2uF
C25 "GRM188R71A225KE15D" 0603L 1445,2200 r90 top value=2.2uF
C26 "GCM32DC72A475KE02L" 1210_220 343.94,2280 r180 top value=4.7uF
C27 "GCM32DC72A475KE02L" 1210_220 343.94,2100 r180 top value=4.7uF
C28 "GCM32DC72A475KE02L" 1210_220 343.94,1920 r180 top value=4.7uF
C29 "GCM32DC72A475KE02L" 1210_220 343.94,1740 r180 top value=4.7uF
C30 "CGA2B3X7S2A103K050BB" 0402S 2659.34,1830 r0 top value=0.01uF
C31 "CGA2B3X7S2A103K050BB" 0402S 2659.34,2190 r0 top value=0.01uF
C32 "CGA2B3X7S2A103K050BB" 0402S 2659.34,2010 r0 top value=0.01uF
C33 "CGA2B3X7S2A103K050BB" 0402S 343.94,1830 r180 top value=0.01uF
C34 "CGA2B3X7S2A103K050BB" 0402S 343.94,2190 r180 top value=0.01uF
C35 "CGA2B3X7S2A103K050BB" 0402S 343.94,2010 r180 top value=0.01uF
C36 "CGA3E2X7R1E104K080AA" 0603L 1649.84,2258.59 r270 top value=0.1uF
C37 "CGA3E2X7R1E104K080AA" 0603L 1325.32,2265.07 r270 top value=0.1uF
C38 "UMJ325KB7106KMHT" 1210_270 2656.53,1504.16 r90 top value=10uF
C39 "UMJ325KB7106KMHT" 1210_270 1320,1504.16 r90 top value=10uF
C40 "UMJ325KB7106KMHT" 1210_270 2525,1504.16 r90 top value=10uF
C41 "UMJ325KB7106KMHT" 1210_270 1190,1504.16 r90 top value=10uF
C42 "UMJ325KB7106KMHT" 1210_270 2240,610 r315 top value=10uF
C43 "CGA3E2X7R1H104K080AA" 0603 1993.77,224.91 r0 top value=0.1uF
C44 "06031C221KAT2A" 0603_HV 2098.5,1960.19 r180 bottom value=220pF
C45 "06031C221KAT2A" 0603_HV 840,1950 r0 bottom value=220pF
C46 "CGA3E2X7R1H104K080AA" 0603 1018.32,228.09 r180 top value=0.1uF
C47 "UMJ325KB7106KMHT" 1210_270 387.51,1504.29 r90 top value=10uF
C48 "UMJ325KB7106KMHT" 1210_270 1710.15,1504.16 r90 top value=10uF
C49 "UMJ325KB7106KMHT" 1210_270 518.97,1504.29 r90 top value=10uF
C50 "UMJ325KB7106KMHT" 1210_270 1840.34,1504.16 r90 top value=10uF
C51 "UMJ325KB7106KMHT" 1210_270 740,610 r225 top value=10uF
C52 "CGA3E3X7R1H224K080AB" 0603 2160,1496.39 r270 bottom value=0.22uF
C53 "CGA3E3X7R1H224K080AB" 0603 860,1490 r90 bottom value=0.22uF
C54 "06031A330JAT2A" 0603L 1915.04,2462.09 r270 top value=33pF
C55 "06031A330JAT2A" 0603L 1130.67,2510.9 r0 top value=33pF
C56 "UMJ325KB7106KMHT" 1210_270 2787.72,1504.16 r90 top value=10uF
C57 "UMJ325KB7106KMHT" 1210_270 2930,945.05 r0 top value=10uF
C58 "UMJ325KB7106KMHT" 1210_270 2694.92,741.95 r270 top value=10uF
C59 "UMJ325KB7106KMHT" 1210_270 2536.9,740.53 r270 top value=10uF
C60 "UMJ325KB7106KMHT" 1210_270 1580.06,1504.16 r90 top value=10uF
C61 "UMJ325KB7106KMHT" 1210_270 250.79,1504.16 r90 top value=10uF
C62 "UMJ325KB7106KMHT" 1210_270 170.31,807.93 r225 top value=10uF
C63 "UMJ325KB7106KMHT" 1210_270 370.11,738.56 r270 top value=10uF
C64 "UMJ325KB7106KMHT" 1210_270 510.78,738.43 r270 top value=10uF
C65 "UMJ325KB7106KMHT" 1210_270 1450,1504.16 r90 top value=10uF
C66 "CGA3E1X7R1E105K080AC" 0603S 1885,2738.57 r180 top value=1uF
C67 "CL10B224KO8VPNC" 0603L 1660,2680 r90 top value=0.22uF
C68 "CL10B224KO8VPNC" 0603L 1600,2680 r90 top value=0.22uF
C69 "CGA3E2NP01H101J080AA" 0603 1788.89,2552.19 r0 top value=100pF
C70 "GRM1885C1H332JA01D" 0603 1788.89,2605.32 r0 top value=3300pF
C71 "GCM188R71H103KA37D" 0603 3642.97,2215.63 r270 bottom value=0.01uF
D1 "SMBJ150A-13-F" SMB 4070.05,2499.83 r180 top value=150V
D2 "1N4148WS-7-F" SOD-323 3936.22,2649.32 r0 bottom value=75V
D3 "SMBJ33CA-13-F" SMB-Bi 3790.81,2499.83 r180 top value=33V
D4 "LTST-C190GKT" LED_LTST-C190 3826.69,1464.36 r180 top value=Green
D5 "1N4148WS-7-F" SOD-323 4406.71,1983.19 r0 top value=75V
D6 "MM3Z4V7ST1G" SOD-323 3665.81,2443.59 r180 bottom value=4.7V
D7 "MMSZ5263BT1G" SOD-123 4230.87,2069.69 r180 top value=56V
D8 "LTST-C170KRKT" LED_LTST-C170_Red 3447.56,2456.08 r270 top value=Red
D9 "BAT46WJ,115" SOD-323F 1645.22,2127.18 r270 top value=100V
D10 "BAT46WJ,115" SOD-323F 1327.71,2132.07 r270 top value=100V
D11 "BAT46WJ,115" SOD-323F 1737.15,2723.02 r90 top value=100V
J1 "1714971" Phoenix_1714971 3942.7,3127.52 r180 top
J2 "1040" CONN_1040 1505,2005 r270 top
J3 "EM292902-UL" Eaton_EM292902 1510,414.96 r0 top
J4 "TSW-114-07-G-S" TSW-114-07-G-S 1510,3045 r0 top
L1 "XAL1060-122MEB" XAL1060 4249.31,993.67 r270 top value=1.2uH
L2 "XGL1010-682MED" FP-XGL1010-103MED_SMT_IND_10MM0_11MM3-MFG 2172.87,1652.44 r270 top value=6.8uH
L3 "XGL1010-682MED" FP-XGL1010-103MED_SMT_IND_10MM0_11MM3-MFG 853.65,1650.58 r270 top value=6.8uH
NT1 "Net-Tie" Net-Tie_10mil 1499.84,2520 r270 top net-tie
Q1 "NVMFS5C612NT1G" FP-NVMFS5C612NT1G_DFN5-MFG 4511.71,1724.32 r180 top
Q2 "IPB320N20N3 G" DDPAK 4642.81,2452.32 r90 top value=200V
Q3 "2N7002KW" SOT-323 3531.71,2148.77 r270 bottom value=60V
Q4 "PMBT5551,215" SOT-23 3756.71,2649.32 r0 bottom value="160 V"
Q5 "NVMFS5C670NLWFAFT1G" SO-8FL 2380,2010 r0 top value=60V
Q6 "NVMFS5C670NLWFAFT1G" SO-8FL 640,2010 r180 top value=60V
Q7 "NVMFS5C670NLWFAFT1G" SO-8FL 2040,2010 r0 top value=60V
Q8 "NVMFS5C670NLWFAFT1G" SO-8FL 980,2010 r180 top value=60V
R1 "WSL20101L000FEA" 2010 4525.29,1448.56 r270 top value=0.001
R2 "CRCW060312K0JNEA" 0603 3942.41,1464.36 r180 top value=12k
R3 "ERJ-3GEY0R00V" 0603 4339.22,1829.44 r180 top value=0
R4 "CRCW0603100KFKEA" 0603 3668.28,2019.32 r90 bottom value=100k
R5 "ERJ-3GEY0R00V" 0603 4406.71,2174.76 r270 top value=0
R6 "TLRH3AWTTER120F" FP-TLRH3AWTTER120F_2512-MFG 4400,245.21 r180 top
R7 "TLRH3AWTTER120F" FP-TLRH3AWTTER120F_2512-MFG 3200,242.61 r0 top
R8 "ERJ-6ENF2002V" 0805_HV 3749.82,2529.1 r180 bottom value=20.0k
R9 "CRCW06034K75FKEA" 0603 3719.28,2152.52 r90 bottom value=4.75k
R10 "CRCW120610K0JNEA" 1206 4237.84,2178.22 r0 top value=10k
R11 "CRCW0603464RFKEA" 0603 4091.71,1694.32 r180 top value=1.82k
R12 "CRCW060350R0FKEA" 0603 4186.71,1729.32 r90 top value=50
R13 "CRCW0603100KFKEA" 0603 3882.75,2162.47 r180 bottom value=100k
R14 "CRCW06031K74FKEA" 0603 3881.71,2082.32 r0 bottom value=1.74k
R15 "RMCF0603FT10K0" 0603 3767.9,2014.7 r270 bottom value=10.0k
R16 "CRCW120610K0JNEA" 1206 3447.56,2268.36 r90 top value=10k
R17 "CRCW06031K10FKEA" 0603 3786.12,2170.81 r90 bottom value=1.07k
R18 "CRCW0603100RJNEA" 0603 3856.98,1700.32 r270 top value=100
R19 "RMCF0603FT10K0" 0603 3767.9,2014.7 r270 top value=10.0k
R20 "RC0603FR-0736KL" 0603 3559.25,1884.48 r0 bottom value=3.48k
R21 "CRCW060324K3FKEA" 0603 3559.25,1804.32 r180 bottom value=15.4k
R22 "RC0603FR-071RL" 0603L 1130,2404.43 r180 top value=1.00
R23 "ERJ-2GE0R00X" 0402L 1698.43,2325.25 r180 top value=0
R24 "ERJ-2GE0R00X" 0402L 1285,2330.16 r180 top value=0
R25 "CRCW0603100KFKEA" 0603L 2240.28,1959.76 r180 bottom value=100k
R26 "ERJ-2GE0R00X" 0402L 1697.11,2365.74 r180 top value=0
R27 "ERJ-2GE0R00X" 0402L 1283.59,2369.38 r180 top value=0
R28 "CRCW0603100KFKEA" 0603L 810,2030 r90 bottom value=100k
R29 "CRCW060310K5FKEA" 0603 2160,1621.5 r90 bottom value=10.5k
R30 "CRCW060310K5FKEA" 0603 860,1620 r270 bottom value=10.5k
R31 "ERJ-6GEYJ2R2V" 0805_HV 2110,2043.01 r180 bottom value=2.2
R32 "ERJ-6GEYJ2R2V" 0805_HV 925,2031.81 r180 bottom value=2.2
R33 "RMCF0603FT10K0" 0603 2099.64,1496.39 r90 bottom value=10.0k
R34 "RMCF0603FT10K0" 0603 930,1490 r270 bottom value=10.0k
R35 "CRCW0603100KFKEA" 0603L 1900,1840 r180 bottom value=100k
R36 "CRCW0603100KFKEA" 0603L 1180,2140 r180 bottom value=100k
R37 "CRCW06030000Z0EA" 0603L 1861.65,2463.44 r270 top value=0
R38 "CRCW0603100RFKEA" 0603L 1860,2366.1 r180 top value=100
R39 "CRCW0603100RFKEA" 0603L 1131.67,2457.56 r180 top value=100
R40 "CRCW06030000Z0EA" 0603L 1021.61,2486.14 r270 top value=0
R41 "CRCW060347K5FKEA" 0603L 1779.73,2440.21 r0 top value=47.5k
R42 "CRCW06031K05FKEA" 0603L 1888.06,2912.07 r180 top value=1.05k
R43 "CRCW06034K32FKEA" 0603L 1888.06,2850.31 r0 top value=4.32k
R44 "CRCW0603100KFKEA" 0603L 1112.97,2965 r180 bottom value=100k
R45 "CRCW0603100KFKEA" 0603L 1112.97,3130 r180 bottom value=100k
R46 "CRCW0603100KFKEA" 0603L 960,3150.67 r90 bottom value=100k
R47 "CRCW0603100KFKEA" 0603L 1933.74,3145 r0 bottom value=100k
R48 "CRCW060354K9FKEA" 0603L 1400,2680 r270 top value=54.9k
R49 "CRCW060311K5FKEA" 0603 1710,2575 r270 top value=11.5k
R50 "CRCW0603976RFKEA" 0603 1780,2495 r180 top value=976
R51 "CRCW06030000Z0EA" 0603L 1341.6,2680 r90 top value=0
SH-J1 "M7582-05" Harwin_M7582-05 1410,3045 r0 top
TP1 "5015" Testpoint_Keystone_Miniature 4525.29,3131.32 r270 top
TP2 "5015" Testpoint_Keystone_Miniature 3339.99,3127.52 r270 top
TP3 "5015" Testpoint_Keystone_Miniature 978.7,2290.81 r90 top
TP4 "5015" Testpoint_Keystone_Miniature 920,460 r90 top
TP5 "5015" Testpoint_Keystone_Miniature 2100,460 r270 top
U1 "LM74930QRGEQ1" RGE0024T-MFG 3931.71,1894.32 r270 top locked
U2 "LM5143QRHARQ1" RHA0040N-MFG 1490,2430 r0 top

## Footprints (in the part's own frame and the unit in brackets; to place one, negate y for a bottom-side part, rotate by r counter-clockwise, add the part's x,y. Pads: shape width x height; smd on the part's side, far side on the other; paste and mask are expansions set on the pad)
0402L [mm] "0402 from SM-752 data"
  rect 0.6x0.5 smd: 1(-0.5,0) 2(0.5,0)
  body extent -0.55,-0.3 0.55,0.3, height 0.6
0402S [mil] "Based on C0402S footprint from PADS legacy"
  rect 15x24 smd: 1(-20,0) 2(20,0)
  body extent -22,-12 22,12, height 24
0603 [mm] "0603 from SM-752 data"
  rect 1x0.95 smd: 1(-0.8,0) 2(0.8,0)
  silkscreen extent -1.52,-0.69 1.52,0.69, body extent -0.87,-0.47 0.87,0.47, height 1
0603_HV [mil] "Ernesto recommended land pattern.  26 mil between pads."
  rect 30x30 smd: 1(-28,0) 2(28,0)
  silkscreen extent -52,-24 52,24, body extent -34,-19 34,19, height 39
0603L [mm] "0603 from SM-752 data"
  rect 0.8x0.85 smd: 1(-0.7,0) 2(0.7,0)
  silkscreen extent -0.07,-0.33 0.07,0.33, body extent -0.87,-0.47 0.87,0.47, height 1
0603S [mil]
  rect 20x35 smd: 1(-30,0) 2(30,0)
  body extent -34,-19 34,19, height 39
0805_HV [mil] "0805 with 30mil clearance between pads"
  rect 50x63 smd: 1(-40,0) 2(40,0)
  silkscreen extent -74,-40 74,40, body extent -43,-29 43,29, height 57
0805L [mm] "0805 from SM-752 data"
  rect 1.1x1.4 smd: 1(-0.75,0) 2(0.75,0)
  body extent -1.1,-0.72 1.1,0.72, height 1.45
1206 [mm] "1206 from SM-752 data"
  rect 1.3x1.85 smd: 1(-1.45,0) 2(1.45,0)
  silkscreen extent -2.4,-1.21 2.4,1.21, body extent -1.7,-0.9 1.7,0.9, height 1.35
1206_180 [mm] "1206_180"
  rect 1.1x1.6 smd: 1(-1.7,0) 2(1.7,0)
  silkscreen extent -0.9,-1 0.9,1, body extent -1.75,-0.95 1.75,0.95, height 1.8
1210_220 [mm] "1210"
  rect 1.3x2.7 smd: 1(-1.45,0) 2(1.45,0)
  silkscreen extent -2.32,-1.57 2.32,1.57, body extent -1.7,-1.35 1.7,1.35, height 2.2
1210_270 [mm] "1210"
  rect 1.3x2.7 smd: 1(-1.45,0) 2(1.45,0)
  silkscreen extent -2.32,-1.57 2.32,1.57, body extent -1.7,-1.35 1.7,1.35, height 2.7
2010 [mm] "Chip Capacitor, Body 5.08x2.54mm, IPC Medium Density"
  rect 1.6x2.7 smd: 1(-2.3,0) 2(2.3,0)
  silkscreen extent -3.42,-1.65 3.42,1.65, body extent -2.73,-1.45 2.73,1.45, height 1.66
CONN_1040 [mil] "Test Point, PC  test point Terminal"
  round 75 hole 52: 1(0,0)
  body extent -55,-12 55,13, height 276
DDPAK [mil] "D2-PAK, 3-Pads, Body 9.7x10.4mm (max), TO-263AB, using Vishay Silionix recommended pad sizes"
  rrect8% 135x49.49 smd mask+1.97: 1(-246.06,100) 3(-246.06,-100)
  rrect1% 355x420 smd paste-181.1 mask+1.97: 2(155.51,0)
  silkscreen extent -335,-202 -43,202, body extent -295,-202 324,202, height 180
Eaton_EM292902 [mm] "Terminal Block, 10.16mm, 2x1, TH"
  rrect4% 2.6x2.6 hole 1.7 paste-2539.97 mask+0: 1(-5.08,-2.68)
  round 2.6 hole 1.7 paste-2539.97 mask+0: 1(-5.08,7.48) 2(5.08,-2.68) 2(5.08,7.48)
  round 2 hole 2 unplated paste-2539.97 mask+0: ""(0,-4.5) ""(0,0) ""(0,4.7)
  silkscreen extent -10.17,-10.02 10.17,9.98, body extent -10.27,-10.12 10.27,10.08, height 0.25
FP-NVMFS5C612NT1G_DFN5-MFG [mm]
  rrect13% 0.75x1 smd paste+0 mask+0: 1(-1.905,-2.748) 2(-0.635,-2.748) 3(0.635,-2.748) 4(1.905,-2.748)
  round 3.631 smd paste+0 mask+0: 5-6(0.021,0.735)
  Top Layer region: -2.28,-1.282 -2.28,-0.857 -2.775,-0.857 -2.775,0.048 -2.28,0.048 -2.28,3.247 -1.53,3.247 -1.53,2.772 1.53,2.772 1.53,3.247 2.28,3.247 2.28,0.048 2.775,0.048 2.775,-0.857 2.28,-0.857 2.28,-1.282
  silkscreen extent -2.73,-3.95 2.73,3.05, body extent -2.88,-3.35 2.88,3.35, height 0.25
FP-TLRH3AWTTER120F_2512-MFG [mm]
  rrect6% 1.55x3.7 smd paste+0 mask+0: 1(-2.975,0) 2(2.975,0)
  silkscreen extent -1.83,-1.7 1.82,1.7, body extent -3.85,-1.95 3.85,1.95, height 0.25
FP-XGL1010-103MED_SMT_IND_10MM0_11MM3-MFG [mm]
  rrect4% 2.38x8.5 smd paste+0 mask+0: 1(-3.325,0) 2(3.325,0)
  silkscreen extent -5.87,-5.9 5.25,5.9, body extent -5.35,-6 5.35,6, height 0.25
Harwin_M7582-05 [mil] "Single Operation 2.54mm Pitch Open Top Jumper Socket"
  body extent -98,-47 98,47, height 236
LED_LTST-C170_Red [mm] "LITE-ON"
  rect 1.2x1.2 smd: 1(-1.05,0) 2(1.05,0)
  silkscreen extent -1.6,-1 2.2,1, body extent -1.05,-0.67 1.05,0.67, height 1.1
LED_LTST-C190 [mm] "Lite-On"
  rect 0.8x0.8 smd: 1(-0.75,0) 2(0.75,0)
  silkscreen extent -1.1,-0.8 1.8,0.8, body extent -0.85,-0.45 0.85,0.45, height 0.9
Net-Tie_10mil [mil] "10mil net tie, no solder mask opening, no solder paste"
  rect 10x10 smd paste-5 mask-5: 1(-10,0) 2(10,0)
  Top Layer region: -6,5 6,5 6,-5 -6,-5
Phoenix_1714971 [mm] "Receptacle, 9.52mm, 2x1, TH"
  rect 1.8x1.8 hole 1.3: 1(-4.76,0)
  round 1.8 hole 1.3: 2(4.76,0)
  silkscreen extent -10.08,-7.89 9.53,4.61, body extent -10.09,-7.9 9.52,4.6, height 22
RGE0024T-MFG [mm]
  rrect40% 0.6x0.25 smd paste+0 mask+0: 1(-1.9,1.25) 2(-1.9,0.75) 3(-1.9,0.25) 4(-1.9,-0.25) 5(-1.9,-0.75) 6(-1.9,-1.25) 13(1.9,-1.25) 14(1.9,-0.75) 15(1.9,-0.25) 16(1.9,0.25) 17(1.9,0.75) 18(1.9,1.25)
  rrect40% 0.25x0.6 smd paste+0 mask+0: 7(-1.25,-1.9) 8(-0.75,-1.9) 9(-0.25,-1.9) 10(0.25,-1.9) 11(0.75,-1.9) 12(1.25,-1.9) 19(1.25,1.9) 20(0.75,1.9) 21(0.25,1.9) 22(-0.25,1.9) 23(-0.75,1.9) 24(-1.25,1.9)
  rrect5% 2.1x2.1 smd paste-1000 mask+0: 25(0,0)
  silkscreen extent -2.9,-2.05 2.05,2.05, body extent -2.3,-2.3 2.3,2.3, height 0.25
RHA0040N-MFG [mm]
  rrect40% 0.6x0.25 smd paste+0 mask+0: 1(-2.9,2.25) 2(-2.9,1.75) 3(-2.9,1.25) 4(-2.9,0.75) 5(-2.9,0.25) 6(-2.9,-0.25) 7(-2.9,-0.75) 8(-2.9,-1.25) 9(-2.9,-1.75) 10(-2.9,-2.25) 21(2.9,-2.25) 22(2.9,-1.75) 23(2.9,-1.25) 24(2.9,-0.75) 25(2.9,-0.25) 26(2.9,0.25) 27(2.9,0.75) 28(2.9,1.25) 29(2.9,1.75) 30(2.9,2.25)
  rrect40% 0.25x0.6 smd paste+0 mask+0: 11(-2.25,-2.9) 12(-1.75,-2.9) 13(-1.25,-2.9) 14(-0.75,-2.9) 15(-0.25,-2.9) 16(0.25,-2.9) 17(0.75,-2.9) 18(1.25,-2.9) 19(1.75,-2.9) 20(2.25,-2.9) 31(2.25,2.9) 32(1.75,2.9) 33(1.25,2.9) 34(0.75,2.9) 35(0.25,2.9) 36(-0.25,2.9) 37(-0.75,2.9) 38(-1.25,2.9) 39(-1.75,2.9) 40(-2.25,2.9)
  rrect3% 3.3x3.3 smd paste-1000 mask+0: 41(0,0)
  silkscreen extent -3.87,-3.05 3.05,3.05, body extent -3.3,-3.3 3.3,3.3, height 0.25
SM_RADIAL_10BMM [mm] "Nichicon 10x10"
  rect 4x2.5 smd: 1(-4,0) 2(4,0)
  silkscreen extent -5.25,-5.25 5.25,5.25, body extent -5.25,-5.25 5.25,5.25, height 10.5
SMB [mil] "Molded Diode, 2-Leads, Body 5.4x3.6mm, IPC Medium Density, based on OnSemi component dimensions"
  rect 85x107.99 smd: 1(-87.01,0) 2(87.01,0)
  silkscreen extent -155,-82 125,82, body extent -106,-71 106,71, height 91
SMB-Bi [mil] "Molded Diode, 2-Leads, Body 5.4x3.6mm, IPC Medium Density, based on OnSemi component dimensions"
  rect 85x107.99 smd: 1(-87.01,0) 2(87.01,0)
  silkscreen extent -125,-79 125,79, body extent -104,-73 104,73, height 89
SO-8FL [mm] "ON SEMICONDUCTOR, DFN5 5x6, 1.27P, CASE 488AA"
  rect 1x0.75 smd: 1(-2.795,1.905) 2(-2.795,0.635) 3(-2.795,-0.635) 4(-2.795,-1.905)
  rect 4.055x4.56 smd: 5(0.698,0)
  Top Layer region: 3.2,-2.28 3.2,-1.53 2.65,-1.53 2.65,-2.28
  Top Layer region: 3.2,1.53 3.2,2.28 2.655,2.28 2.655,1.53
  Top Layer region: 0,-2.775 0,2.775 -0.905,2.775 -0.905,-2.775
  silkscreen extent -3.1,-2.6 3.1,2.9, body extent -3.17,-2.67 3.17,2.67, height 1.11
SOD-123 [mm] "On Semi recommended land pattern"
  rect 0.915x1.22 smd: 1(-1.637,0) 2(1.637,0)
  silkscreen extent -2.74,-1.17 2.03,1.17, body extent -1.93,-0.9 1.93,0.9, height 1.35
SOD-323 [mm] "NXP recommended land pattern"
  rect 0.6x0.6 smd paste-0.05: 1(-1.1,0) 2(1.1,0)
  silkscreen extent -2.06,-0.86 1.53,0.86, body extent -1.3,-0.67 1.3,0.68, height 1.1
SOD-323F [mm] "NXP recommended land pattern"
  rect 0.6x0.6 smd paste-0.05: 1(-1.1,0) 2(1.1,0)
  silkscreen extent -2.06,-0.86 1.53,0.86, body extent -1.35,-0.67 1.35,0.68, height 0.79
SOT-23 [mm] "SOT23, 3-Leads, Body 2.9x1.3mm, Pitch 0.95mm, Lead Span 2.5mm, IPC Medium Density"
  rrect50% 1x0.6 smd: 1(-1.2,0.95) 2(-1.2,-0.95) 3(1.2,0)
  silkscreen extent -1.63,-1.5 0.7,1.5, body extent -1.16,-1.45 1.21,1.45, height 1
SOT-323 [mm] "Diodes Inc recommended land pattern.  2016-02-24"
  rrect21% 0.6x0.47 smd: 1(-0.95,0.65) 2(-0.95,-0.65) 3(0.95,0)
  silkscreen extent -1.14,-1.22 0.77,1.22, body extent -1.13,-1.13 1.12,1.12, height 1.13
Testpoint_Keystone_Miniature [mil] "Miniature SMT test point"
  rect 135x70 smd: 1(0,0)
  silkscreen extent -78,-46 78,45, body extent -52,-20 52,20, height 61
TSW-114-07-G-S [mm] "Samtec 100mil, 1x14, 230 mil above insulator"
  rrect6% 1.65x1.65 hole 1.016: 1(-16.51,0)
  round 1.65 hole 1.016: 2(-13.97,0) 3(-11.43,0) 4(-8.89,0) 5(-6.35,0) 6(-3.81,0) 7(-1.27,0) 8(1.27,0) 9(3.81,0) 10(6.35,0) 11(8.89,0) 12(11.43,0) 13(13.97,0) 14(16.51,0)
  silkscreen extent -17.78,-1.27 17.78,1.65, body extent -17.78,-1.27 17.78,1.27, height 8.38
XAL1060 [mm] "COILCRAFT"
  rect 2.39x11 smd: 1(-3.325,0) 2(3.325,0)
  silkscreen extent -5.3,-6 5.3,6, body extent -5.25,-5.9 5.25,5.9, height 6

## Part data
C1: library part CMP-0860999-1, "CAP, CERM, 0.1 µF, 100 V,+/- 10%, X8L, AEC-Q200 Grade 0, 0603", Cap_Case=0603, Manufacturer=MuRata, TempCo=X8L, Tolerance_%=10%, Value2=100V, ValueDisplayed=0.1µF
C2 C3: library part CMP-0012603-3, "CAP, Polymer Hybrid, 56 uF, 63 V, +/- 20%, 30 ohm, 10x10 SMD", Manufacturer=Panasonic, Supplier Part Number 1=P15469CT-ND, Tolerance_%=20%, Value1="30 ohm", Value2=63V, ValueDisplayed=56uF
C4 C6: library part CMP-0007722-2, "CAP, CERM, 0.1 uF, 100 V, +/- 10%, X7R, 0805", Cap_Case=0805, Manufacturer=Kemet, Supplier Part Number 1=399-3486-1-ND, TempCo=X7R, Tolerance_%=10%, Value1="0.064 ohm", Value2=100V, ValueDisplayed=0.1uF
C5 C7 C8 C20 C21 C22 C23 C26 C27 C28 C29: library part CMP-0082268-1, "CAP, CERM, 4.7 µF, 100 V,+/- 10%, X7S, AEC-Q200 Grade 1, 1210", Cap_Case=1210, Manufacturer=MuRata, Supplier Part Number 1=490-14484-1-ND, TempCo=X7S, Tolerance_%=10%, Value1="0.001 ohm", Value2=100V, ValueDisplayed=4.7µF
C9 C36 C37: library part CMP-0007077-5, "CAP, CERM, 0.1 uF, 25 V, +/- 10%, X7R, AEC-Q200 Grade 1, 0603", Cap_Case=0603, Manufacturer=TDK, Supplier Part Number 1=445-5667-1-ND, TempCo=X7R, Tolerance_%=10%, Value1=Unknown, Value2=25V, ValueDisplayed=0.1uF
C10: library part CMP-0083622-1, "CAP, CERM, 2.2 µF, 25 V,+/- 10%, X7R, AEC-Q200 Grade 1, 0805", Cap_Case=0805, Manufacturer=MuRata, Supplier Part Number 1=490-4787-1-ND, TempCo=X7R, Tolerance_%=10%, Value2=25V, ValueDisplayed=2.2µF
C11: library part CMP-0008815-2, "CAP, CERM, 1 uF, 100 V, +/- 10%, X7R, AEC-Q200 Grade 1, 1206", Cap_Case=1206, Manufacturer=MuRata, Supplier Part Number 1=GCM31CR72A105KA03L-ND, TempCo=X7R, Tolerance_%=10%, Value1=Unknown, Value2=100V, ValueDisplayed=1uF
C12: library part CMP-0007418-4, "CAP, CERM, 3300 pF, 25 V, +/- 10%, X7R, 0603", Cap_Case=0603, Manufacturer=MuRata, Supplier Part Number 1=GRM188R71E332KA01D-ND, TempCo=X7R, Tolerance_%=10%, Value1=Unknown, Value2=25V, ValueDisplayed=3300pF
C13: library part CMP-0007143-4, "CAP, CERM, 0.01 uF, 50 V, +/- 10%, X7R, AEC-Q200 Grade 1, 0603", Cap_Case=0603, Manufacturer=MuRata, Supplier Part Number 1=490-4778-1-ND, TempCo=X7R, Tolerance_%=10%, Value1=Unknown, Value2=50V, ValueDisplayed=0.01uF
C14: library part CMP-0006899-4, "CAP, CERM, 0.022 uF, 25 V, +/- 10%, X7R, 0603", Cap_Case=0603, Manufacturer=Kemet, Supplier Part Number 1=399-1094-1-ND, TempCo=X7R, Tolerance_%=10%, Value1=Unknown, Value2=25V, ValueDisplayed=0.022uF
C15: library part CMP-0007082-4, "CAP, CERM, 0.01 uF, 100 V, +/- 10%, X7R, AEC-Q200 Grade 1, 0603", Cap_Case=0603, Manufacturer=TDK, Supplier Part Number 1=445-5812-1-ND, TempCo=X7R, Tolerance_%=10%, Value1="0.235428 ohm", Value2=100V, ValueDisplayed=0.01uF
C16: library part CMP-0007101-4, "CAP, CERM, 0.047 uF, 100 V, +/- 10%, X7S, AEC-Q200 Grade 1, 0603", Cap_Case=0603, Manufacturer=TDK, Supplier Part Number 1=445-6936-1-ND, TempCo=X7S, Tolerance_%=10%, Value1="0.089796 ohm", Value2=100V, ValueDisplayed=0.047uF
C17: library part CMP-0008374-2, "CAP, CERM, 0.47 uF, 100 V, +/- 10%, X7R, 0805", Cap_Case=0805, Manufacturer=MuRata, Supplier Part Number 1=490-3326-1-ND, TempCo=X7R, Tolerance_%=10%, Value1=Unknown, Value2=100V, ValueDisplayed=0.47uF
C18: library part CMP-0007138-4, "CAP, CERM, 0.47 uF, 16 V, +/- 10%, X7R, AEC-Q200 Grade 1, 0603", Cap_Case=0603, Manufacturer=MuRata, Supplier Part Number 1=490-4775-1-ND, TempCo=X7R, Tolerance_%=10%, Value1=Unknown, Value2=16V, ValueDisplayed=0.47uF
C19 C24 C25: library part CMP-0007370-4, "CAP, CERM, 2.2 uF, 10 V, +/- 10%, X7R, 0603", Cap_Case=0603, Manufacturer=MuRata, Supplier Part Number 1=490-4520-1-ND, TempCo=X7R, Tolerance_%=10%, Value1="0.009 ohm", Value2=10V, ValueDisplayed=2.2uF
C30 C31 C32 C33 C34 C35: library part CMP-0006333-2, "CAP, CERM, 0.01 uF, 100 V, +/- 10%, X7S, AEC-Q200 Grade 1, 0402", Cap_Case=0402, Manufacturer=TDK, Supplier Part Number 1=445-6910-1-ND, TempCo=X7S, Tolerance_%=10%, Value1="0.410191 ohm", Value2=100V, ValueDisplayed=0.01uF
C38 C39 C40 C41 C42 C47 C48 C49 C50 C51 C56 C57 C58 C59 C60 C61 C62 C63 C64 C65: library part CMP-0009257-2, "CAP, CERM, 10 uF, 50 V, +/- 10%, X7R, AEC-Q200 Grade 1, 1210", Cap_Case=1210, Manufacturer="Taiyo Yuden", Supplier Part Number 1=587-4279-1-ND, TempCo=X7R, Tolerance_%=10%, Value1=Unknown, Value2=50V, ValueDisplayed=10uF
C43 C46: library part CMP-0007078-4, "CAP, CERM, 0.1 uF, 50 V, +/- 10%, X7R, AEC-Q200 Grade 1, 0603", Cap_Case=0603, Manufacturer=TDK, Supplier Part Number 1=445-5666-1-ND, TempCo=X7R, Tolerance_%=10%, Value1="0.0296 ohm", Value2=50V, ValueDisplayed=0.1uF
C44 C45: library part CMP-0006735-5, "CAP, CERM, 220 pF, 100 V, +/- 10%, X7R, 0603", Cap_Case=0603, Manufacturer=AVX, Supplier Part Number 1=478-1195-1-ND, TempCo=X7R, Tolerance_%=10%, Value1="0.579 ohm", Value2=100V, ValueDisplayed=220pF
C52 C53: library part CMP-0007094-5, "CAP, CERM, 0.22 uF, 50 V, +/- 10%, X7R, AEC-Q200 Grade 1, 0603", Cap_Case=0603, Manufacturer=TDK, Supplier Part Number 1=445-6926-1-ND, TempCo=X7R, Tolerance_%=10%, Value1="0.021699 ohm", Value2=50V, ValueDisplayed=0.22uF
C54 C55: library part CMP-0006722-4, "CAP, CERM, 33 pF, 100 V, +/- 5%, C0G/NP0, 0603", Cap_Case=0603, Manufacturer=AVX, Supplier Part Number 1=478-1143-1-ND, TempCo=C0G/NP0, Tolerance_%=5%, Value1="0.209 ohm", Value2=100V, ValueDisplayed=33pF
C66: library part CMP-0076705-3, "CAP, CERM, 1 µF, 25 V,+/- 10%, X7R, AEC-Q200 Grade 1, 0603", Cap_Case=1.6x0.8x0.8mm, Manufacturer=TDK, Supplier Part Number 1=445-6931-1-ND, TempCo=X7R, Tolerance_%=10%, Value2=25V, ValueDisplayed=1µF
C67 C68: library part CMP-0080102-1, "CAP, CERM, 0.22 µF, 16 V,+/- 10%, X7R, AEC-Q200 Grade 1, 0603", Cap_Case=0603, Manufacturer=Samsung, Supplier Part Number 1=1276-6868-1-ND, TempCo=X7R, Tolerance_%=10%, Value2=16V, ValueDisplayed=0.22µF
C69: library part CMP-0007075-4, "CAP, CERM, 100 pF, 50 V, +/- 5%, C0G/NP0, AEC-Q200 Grade 0, 0603", Cap_Case=0603, Manufacturer=TDK, Supplier Part Number 1=445-12386-1-ND, TempCo=C0G/NP0, Tolerance_%=5%, Value1=Unknown, Value2=50V, ValueDisplayed=100pF
C70: library part CMP-0007210-4, "CAP, CERM, 3300 pF, 50 V, +/- 5%, C0G/NP0, 0603", Cap_Case=0603, Manufacturer=MuRata, Supplier Part Number 1=GRM1885C1H332JA01D-ND, TempCo=C0G/NP0, Tolerance_%=5%, Value1=Unknown, Value2=50V, ValueDisplayed=3300pF
C71: library part CMP-0007143-4, "CAP, CERM, 0.01 uF, 50 V, +/- 10%, X7R, AEC-Q200 Grade 1, 0603 (stack on top of R17 resistor)", Cap_Case=0603, Manufacturer=MuRata, Supplier Part Number 1=490-4778-1-ND, TempCo=X7R, Tolerance_%=10%, Value1=Unknown, Value2=50V, ValueDisplayed=0.01uF
D1: library part CMP-0005577-3, "Diode, TVS, Uni, 150 V, 243 Vc, SMB", Manufacturer="Diodes Inc.", Value1=600W
D2 D5: library part CMP-0079597-2, "Diode, Switching, 75 V, 0.15 A, AEC-Q101, SOD-323", Manufacturer="Diodes Inc.", Value1=0.15A, Value2=1.25V
D3: library part CMP-0005564-3, "Diode, TVS, Bi, 33 V, SMB", Manufacturer="Diodes Inc.", Value1=600W
D4: library part CMP-0002827-3, "LED, Green, SMD", Color=green, Manufacturer=Lite-On, Power_TotalModule=100mW, Value1=0.1W, Value2=2.1V
D6: library part CMP-0085737-1, "Diode, Zener, 4.7 V, 300 mW, SOD-323", Manufacturer="ON Semiconductor", Power_W=300mW, Value1=0.3W
D7: library part CMP-0005738-4, "Diode, Zener, 56 V, 500 mW, AEC-Q101, SOD-123", Manufacturer="ON Semiconductor", Power_W=500mW, Value1=0.5W
D8: library part CMP-0002829-3, "LED, Red, SMD", Color=red, Manufacturer=Lite-On, Value1=W, Value2=2V
D9 D10 D11: library part CMP-0076946-2, "Diode, Schottky, 100 V, 0.25 A, SOD-323F", Manufacturer=Nexperia, Value1=0.25A, Value2=0.85V
J1: library part CMP-0055554-1, "Receptacle, 9.52mm, 2x1, TH", Color=Green, Current_A=32A, Manufacturer="Phoenix Contact", Supplier Part Number 1=277-1271-ND, Voltage_V=1kV
J2: library part CMP-0055161-1, "TEST POINT SLOTTED .118\", TH", Manufacturer=Keystone, Supplier Part Number 1=36-1040-ND
J3: library part CMP-0077513-2, "Terminal Block, 10.16mm, 2x1, Tin, R/A, TH", Color=Green, Current_A=65A, Manufacturer=Eaton, Supplier Part Number 1=283-4339-ND, Voltage_V=300V
J4: library part CMP-0075428-1, "Header, 100mil, 14x1, Gold, TH", Color=Black, Current_A=6.3A, Manufacturer=Samtec, Supplier Part Number 1=SAM1029-14-ND, Voltage_V=550V
L1: library part CMP-0060959-1, "Inductor, Shielded, Composite, 1.2 uH, 26.3 A, 0.0025 ohm, AEC-Q200 Grade 1, SMD", Manufacturer=Coilcraft, Supplier Part Number 1=994-XAL1060-122MEB, Value1="0.0025 ohm", Value2=26.3A, ValueDisplayed=1.2uH
L2 L3: library part CMP-0120510-1, "6.8 µH Shielded Molded Inductor 21.2 A 7.0mOhm Max Nonstandard", Digikey Part Number=2457-XGL1010-103MED-ND, Manufacturer=Coilcraft, Operating Temperature Range=to, Part Number=XGL1010-103MED, Self Resonant Frequency=12MHz, Test Frequency=1MHz, Tolerance_%=20%
NT1: library part CMP-0078142-6, "Single point connection between nets.", Manufacturer=N/A
Q1: library part CMP-0093804-1, "Single N-Channel Power MOSFET 60V, 225A, 1.65ohm", Drain To Source Breakdown Voltage=60V, Input Capacitace At Vds="4900pF @ 25V", Manufacturer=onsemi, Operating Temperature Range="-55°C to +175°C", Power_W=3.8W, Pulse Drain Current=900A, Typ Forward Diode Voltage=0.81V
Q2: library part CMP-0001084-3, "MOSFET, N-CH, 200 V, 34 A, DDPAK", Alternate Manufacturer=None, Manufacturer="Infineon Technologies", Supplier Part Number 1="IPB320N20N3 GCT-ND", Value1=0.2, Value2="22 nC"
Q3: library part CMP-0000774-1, "MOSFET, N-CH, 60 V, 0.31 A, SOT-323", Alternate Manufacturer=None, Manufacturer="Fairchild Semiconductor", Supplier Part Number 1=2N7002KWCT-ND, Value1=1
Q4: library part CMP-0750056-1, "Transistor, NPN, 160 V, 0.3 A, SOT-23", Manufacturer=Nexperia, Value1="0.3 A", Value2=250
Q5 Q6 Q7 Q8: library part CMP-0750168-1, "MOSFET, N-CH, 60 V, 17 A, AEC-Q101, SO-8FL", Alternate Manufacturer=None, Manufacturer="ON Semiconductor", Value1="0.0088 ohm", Value2="20 nC"
R1: library part CMP-0016548-2, "RES, 0.001, 1%, 0.5 W, 2010", Manufacturer=Vishay-Dale, Power_W=500mW, Supplier Part Number 1=WSLE-.001CT-ND, TempCo="275 ppm/C", Tolerance_%=1%, Value2=0.5W, Value_Code=1L000, ValueDisplayed=0.001
R2: library part CMP-0025711-4, "RES, 12 k, 5%, 0.1 W, AEC-Q200 Grade 0, 0603", Manufacturer=Vishay-Dale, Power_W=100mW, Supplier Part Number 1=541-12KGCT-ND, TempCo="200 ppm/C", Tolerance_%=5%, Value2=0.1W, Value_Code=12k0, ValueDisplayed=12k
R3 R5: library part CMP-0025874-4, "RES, 0, 5%, 0.1 W, AEC-Q200 Grade 0, 0603", Manufacturer=Panasonic, Power_W=100mW, Supplier Part Number 1=P0.0GCT-ND, TempCo="600 ppm/C", Tolerance_%=5%, Value2=0.1W, Value_Code=0000, ValueDisplayed=0
R4 R13 R25 R28 R35 R36 R44 R45 R46 R47: library part CMP-0021990-4, "RES, 100 k, 1%, 0.1 W, AEC-Q200 Grade 0, 0603", Manufacturer=Vishay-Dale, Power_W=100mW, Supplier Part Number 1=541-100KHCT-ND, TempCo="100 ppm/C", Tolerance_%=1%, Value2=0.1W, Value_Code=100k
R6 R7: library part CMP-0088454-1, "120 mOhms ±1% 2W Chip Resistor 2512 (6432 Metric) Automotive AEC-Q200, Current Sense Metal Element", Digikey Part Number=2019-TLRH3AWTTER120FCT-ND, Manufacturer="KOA Speer", Mouser Part Number=660-TLRH3AWTTER120F, Operating Temperature Range="-65°C to +170°C", Power_W=2W, TempCo=50ppm/°C, Tolerance_%=1%
R8: library part CMP-0021614-3, "RES, 20.0 k, 1%, 0.125 W, AEC-Q200 Grade 0, 0805", Manufacturer=Panasonic, Power_W=125mW, Supplier Part Number 1=P20.0KCCT-ND, TempCo="100 ppm/C", Tolerance_%=1%, Value2=0.125W, Value_Code=20k0, ValueDisplayed=20.0k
